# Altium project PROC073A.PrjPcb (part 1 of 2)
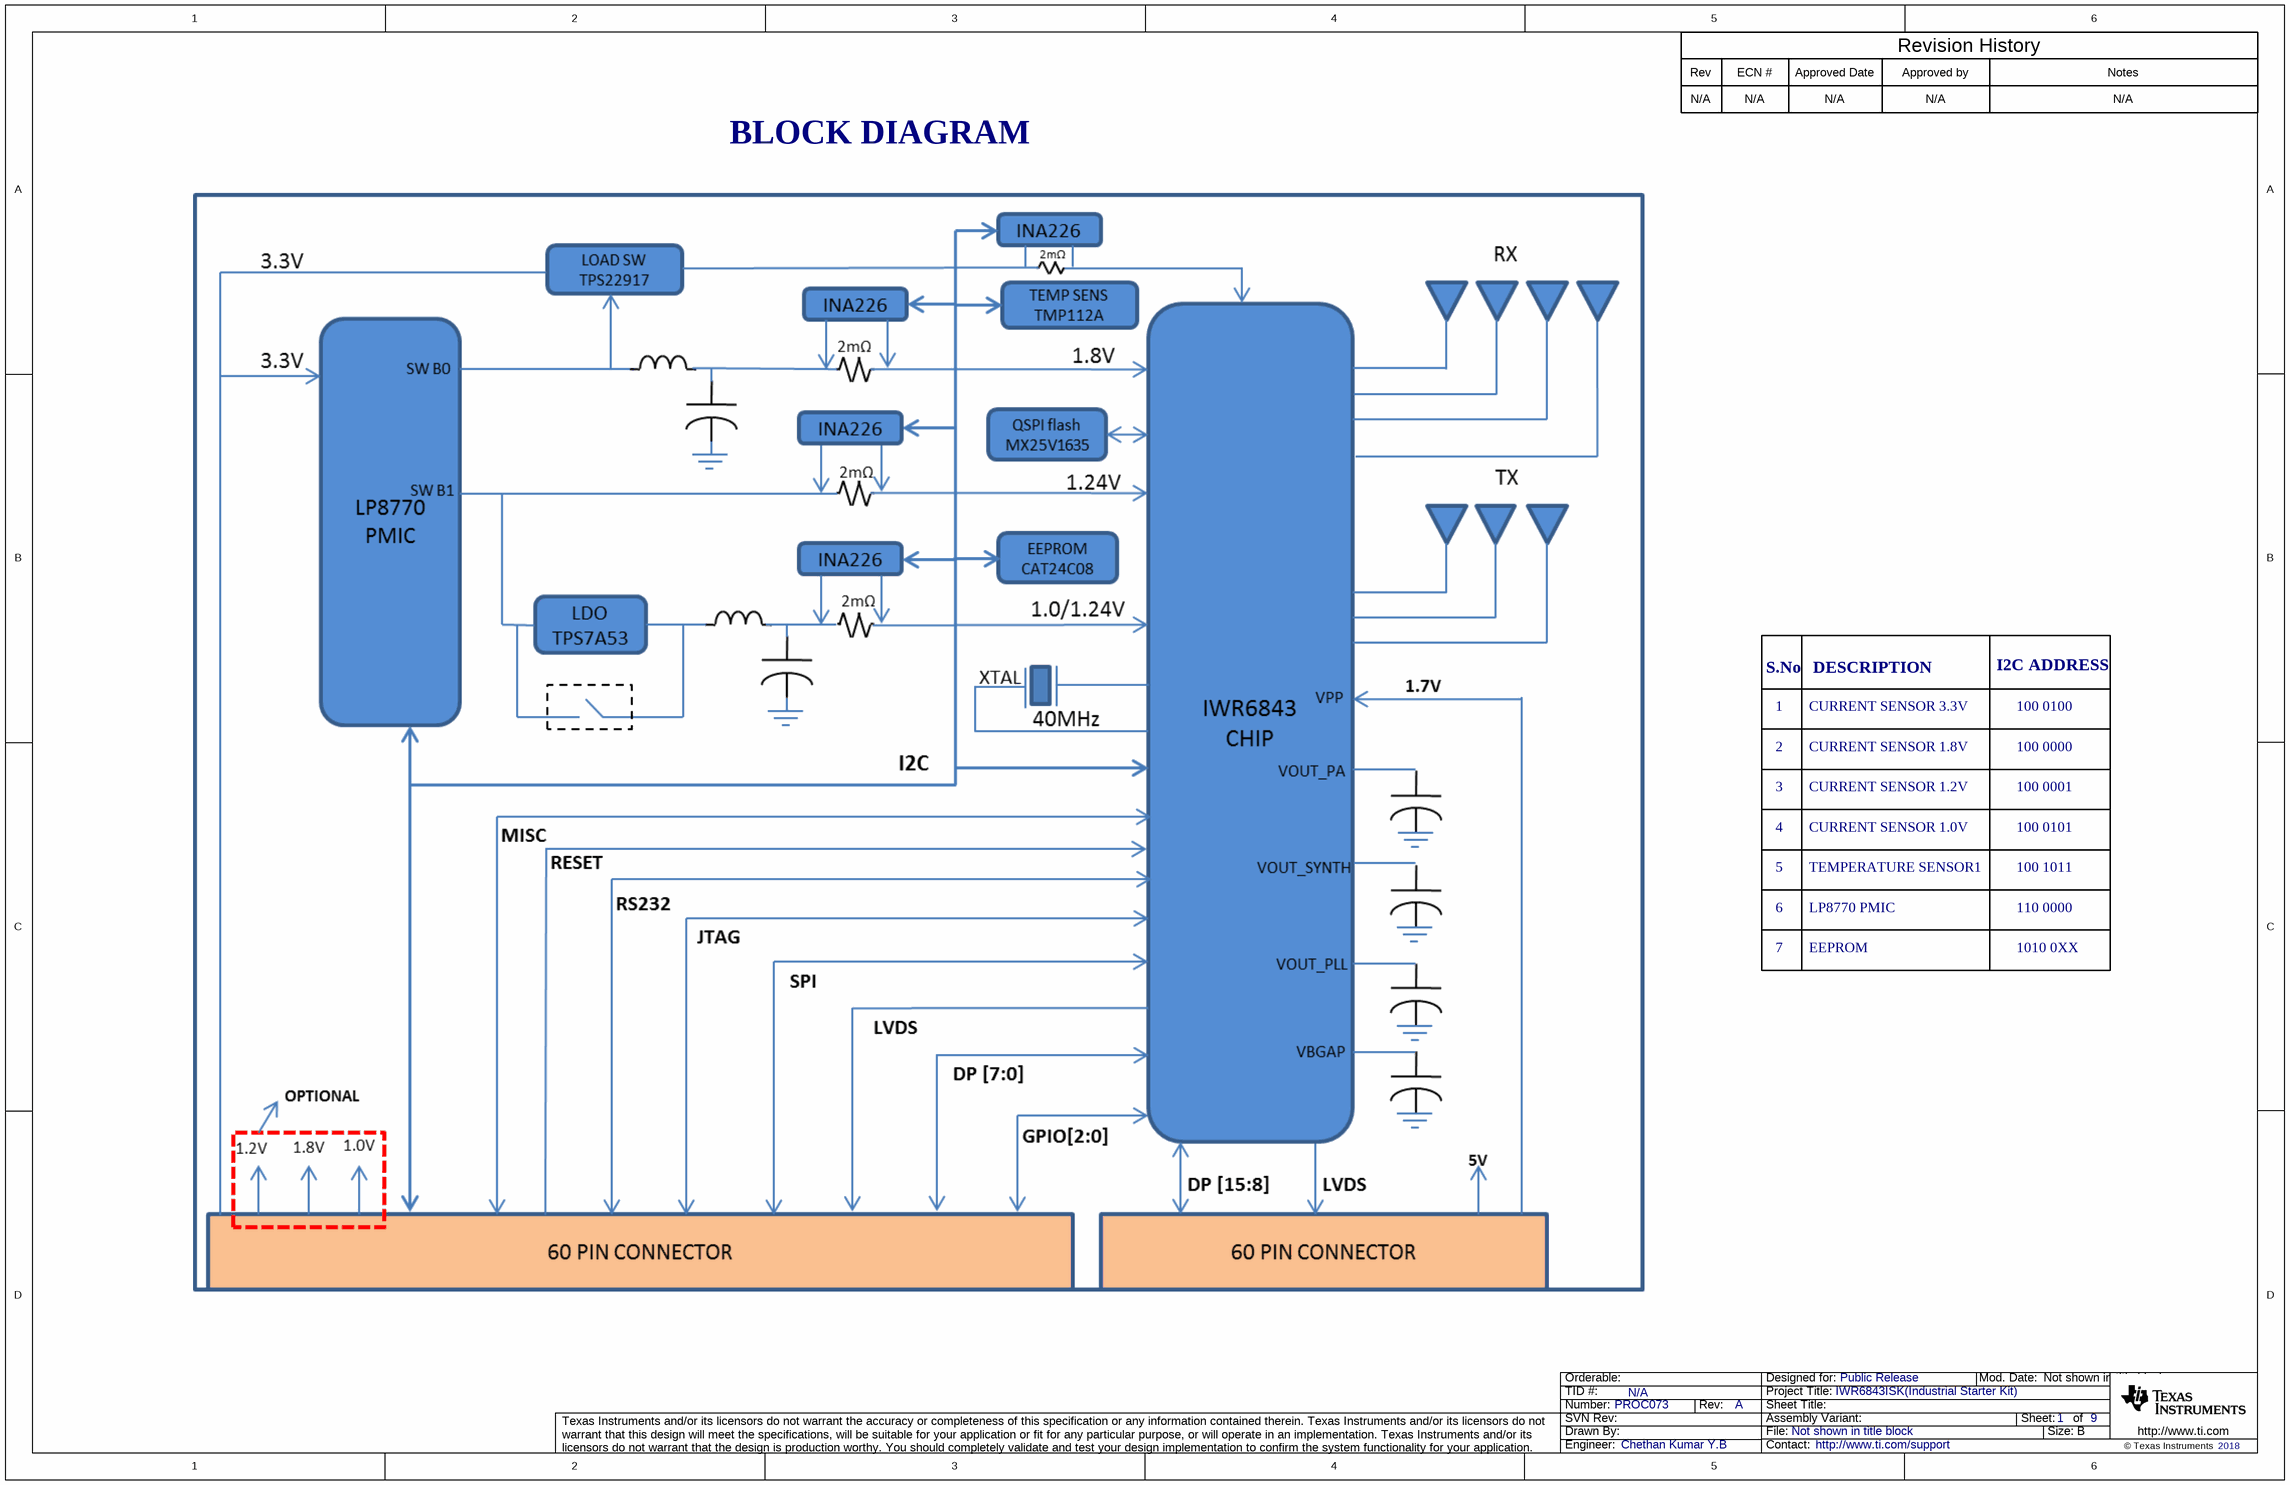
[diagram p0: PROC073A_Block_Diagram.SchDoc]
CopyrightYear: 2018; PCB_Layout: Tessolve; PCB_Rev: A; PRJ_Customer: Public Release; PRJ_Engineer: Chethan Kumar Y.B; PRJ_Number: PROC073; PRJ_Title: IWR6843ISK(Industrial Starter Kit); SCH_Rev: A; TechSupport: http://www.ti.com/support; TID: N/A
9 sheets, 285 parts. Net scope: flat (ports and power ports of the same name join across sheets).
Board file: PROC073A_PCB.PcbDoc
Sheets:
  PROC073A_Block_Diagram.SchDoc
  PROC073A_Table_Of_Contents.SchDoc
  PROC073A_PMIC.SchDoc
  PROC073A_IWR6843_Chip.SchDoc
  PROC073A_Decoupling_caps.SchDoc
  PROC073A_QSPI_Flash_section.SchDoc
  PROC073A_HD_Connector_60Pin.SchDoc
  PROC073A_Temp_Current_sensor.SchDoc
  PROC073A_EVM_Hardware.SchDoc

## Sheet PROC073A_Block_Diagram.SchDoc
size 431 x 279 mm; Date: Not shown in title block; ApprovedBy: Not shown in title block; CheckedBy: Not shown in title block; Author: Not shown in title block; CompanyName: Not shown in title block; Engineer: Not shown in title block; Organization: Not shown in title block; Address1: Not shown in title block; Address2: Not shown in title block; Address3: Not shown in title block; Address4: Not shown in title block; DocumentNumber: 1; Revision: Use project parameter SCH_Rev; SheetNumber: 1; SheetTotal: 9; PageSetup: Record=PageOptions¦CenterHorizontal=True¦CenterVertical=True¦PrintScale=1.00¦XCorrection=1.00¦YCorrection=1.00¦PrintKind=0¦BorderSize=5000000¦LeftOffset=0¦BottomOffset=0¦Orientation=2¦PaperLength=1000¦PaperWidth=1000¦Scale=100¦PaperSource=15¦PrintQuality=600¦MediaType=1¦DitherType=10¦PaperKind=Letter¦PrintScaleMode=1

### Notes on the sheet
- Rev
- N/A
- ECN #
- Approved Date
- Approved by
- Revision History
- Notes
- BLOCK DIAGRAM
- S.No
- DESCRIPTION
- I2C ADDRESS
- 1
- 2
- CURRENT SENSOR 3.3V
- CURRENT SENSOR 1.8V
- 100 0100
- 100 0000
- 3
- 4
- CURRENT SENSOR 1.2V
- CURRENT SENSOR 1.0V
- 100 0001
- 100 0101
- 5
- TEMPERATURE SENSOR1
- 100 1011
- 6
- 7
- LP8770 PMIC
- EEPROM
- 1010 0XX
- 110 0000

## Sheet PROC073A_Table_Of_Contents.SchDoc
size 431 x 279 mm; Date: Not shown in title block; ApprovedBy: Not shown in title block; CheckedBy: Not shown in title block; Author: Not shown in title block; CompanyName: Not shown in title block; Engineer: Not shown in title block; Organization: Not shown in title block; Address1: Not shown in title block; Address2: Not shown in title block; Address3: Not shown in title block; Address4: Not shown in title block; DocumentNumber: 1; Revision: Use project parameter SCH_Rev; SheetNumber: 2; SheetTotal: 9; PageSetup: Record=PageOptions¦CenterHorizontal=True¦CenterVertical=True¦PrintScale=1.00¦XCorrection=1.00¦YCorrection=1.00¦PrintKind=0¦BorderSize=5000000¦LeftOffset=0¦BottomOffset=0¦Orientation=2¦PaperLength=1000¦PaperWidth=1000¦Scale=100¦PaperSource=15¦PrintQuality=600¦MediaType=1¦DitherType=10¦PaperKind=Letter¦PrintScaleMode=1
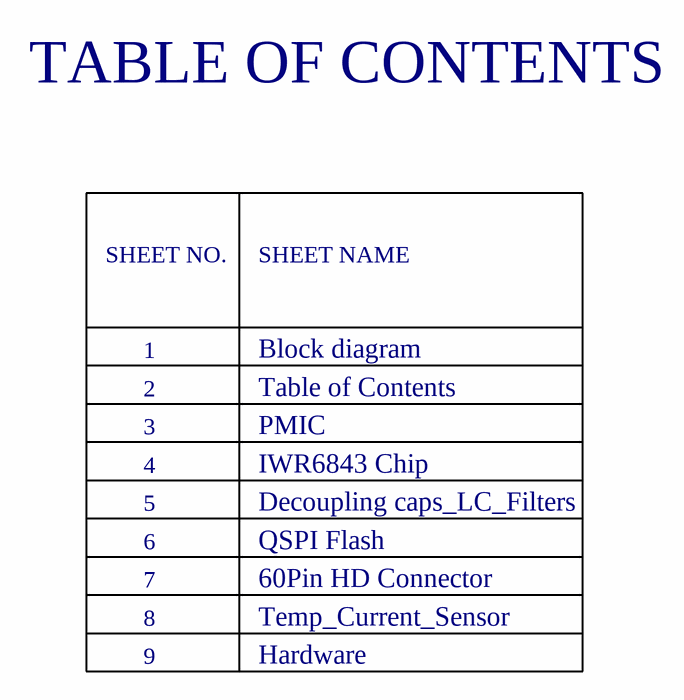
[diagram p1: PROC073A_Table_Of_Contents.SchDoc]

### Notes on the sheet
- TABLE OF CONTENTS
- SHEET NO.
- SHEET NAME
- 1
- 2
- 3
- Table of Contents
- Block diagram
- PMIC
- 4
- 5
- IWR6843 Chip
- Decoupling caps_LC_Filters
- 7
- 8
- 6
- QSPI Flash
- 60Pin HD Connector
- Temp_Current_Sensor
- 9
- Hardware

## Sheet PROC073A_PMIC.SchDoc
size 431 x 279 mm; Date: Not shown in title block; ApprovedBy: Not shown in title block; CheckedBy: Not shown in title block; Author: Not shown in title block; CompanyName: Not shown in title block; Engineer: Not shown in title block; Organization: Not shown in title block; Address1: Not shown in title block; Address2: Not shown in title block; Address3: Not shown in title block; Address4: Not shown in title block; DocumentNumber: 1; Revision: Use project parameter SCH_Rev; SheetNumber: 3; SheetTotal: 9; PageSetup: Record=PageOptions¦CenterHorizontal=True¦CenterVertical=True¦PrintScale=1.00¦XCorrection=1.00¦YCorrection=1.00¦PrintKind=0¦BorderSize=5000000¦LeftOffset=0¦BottomOffset=0¦Orientation=2¦PaperLength=1000¦PaperWidth=1000¦Scale=100¦PaperSource=15¦PrintQuality=600¦MediaType=1¦DitherType=10¦PaperKind=Letter¦PrintScaleMode=1
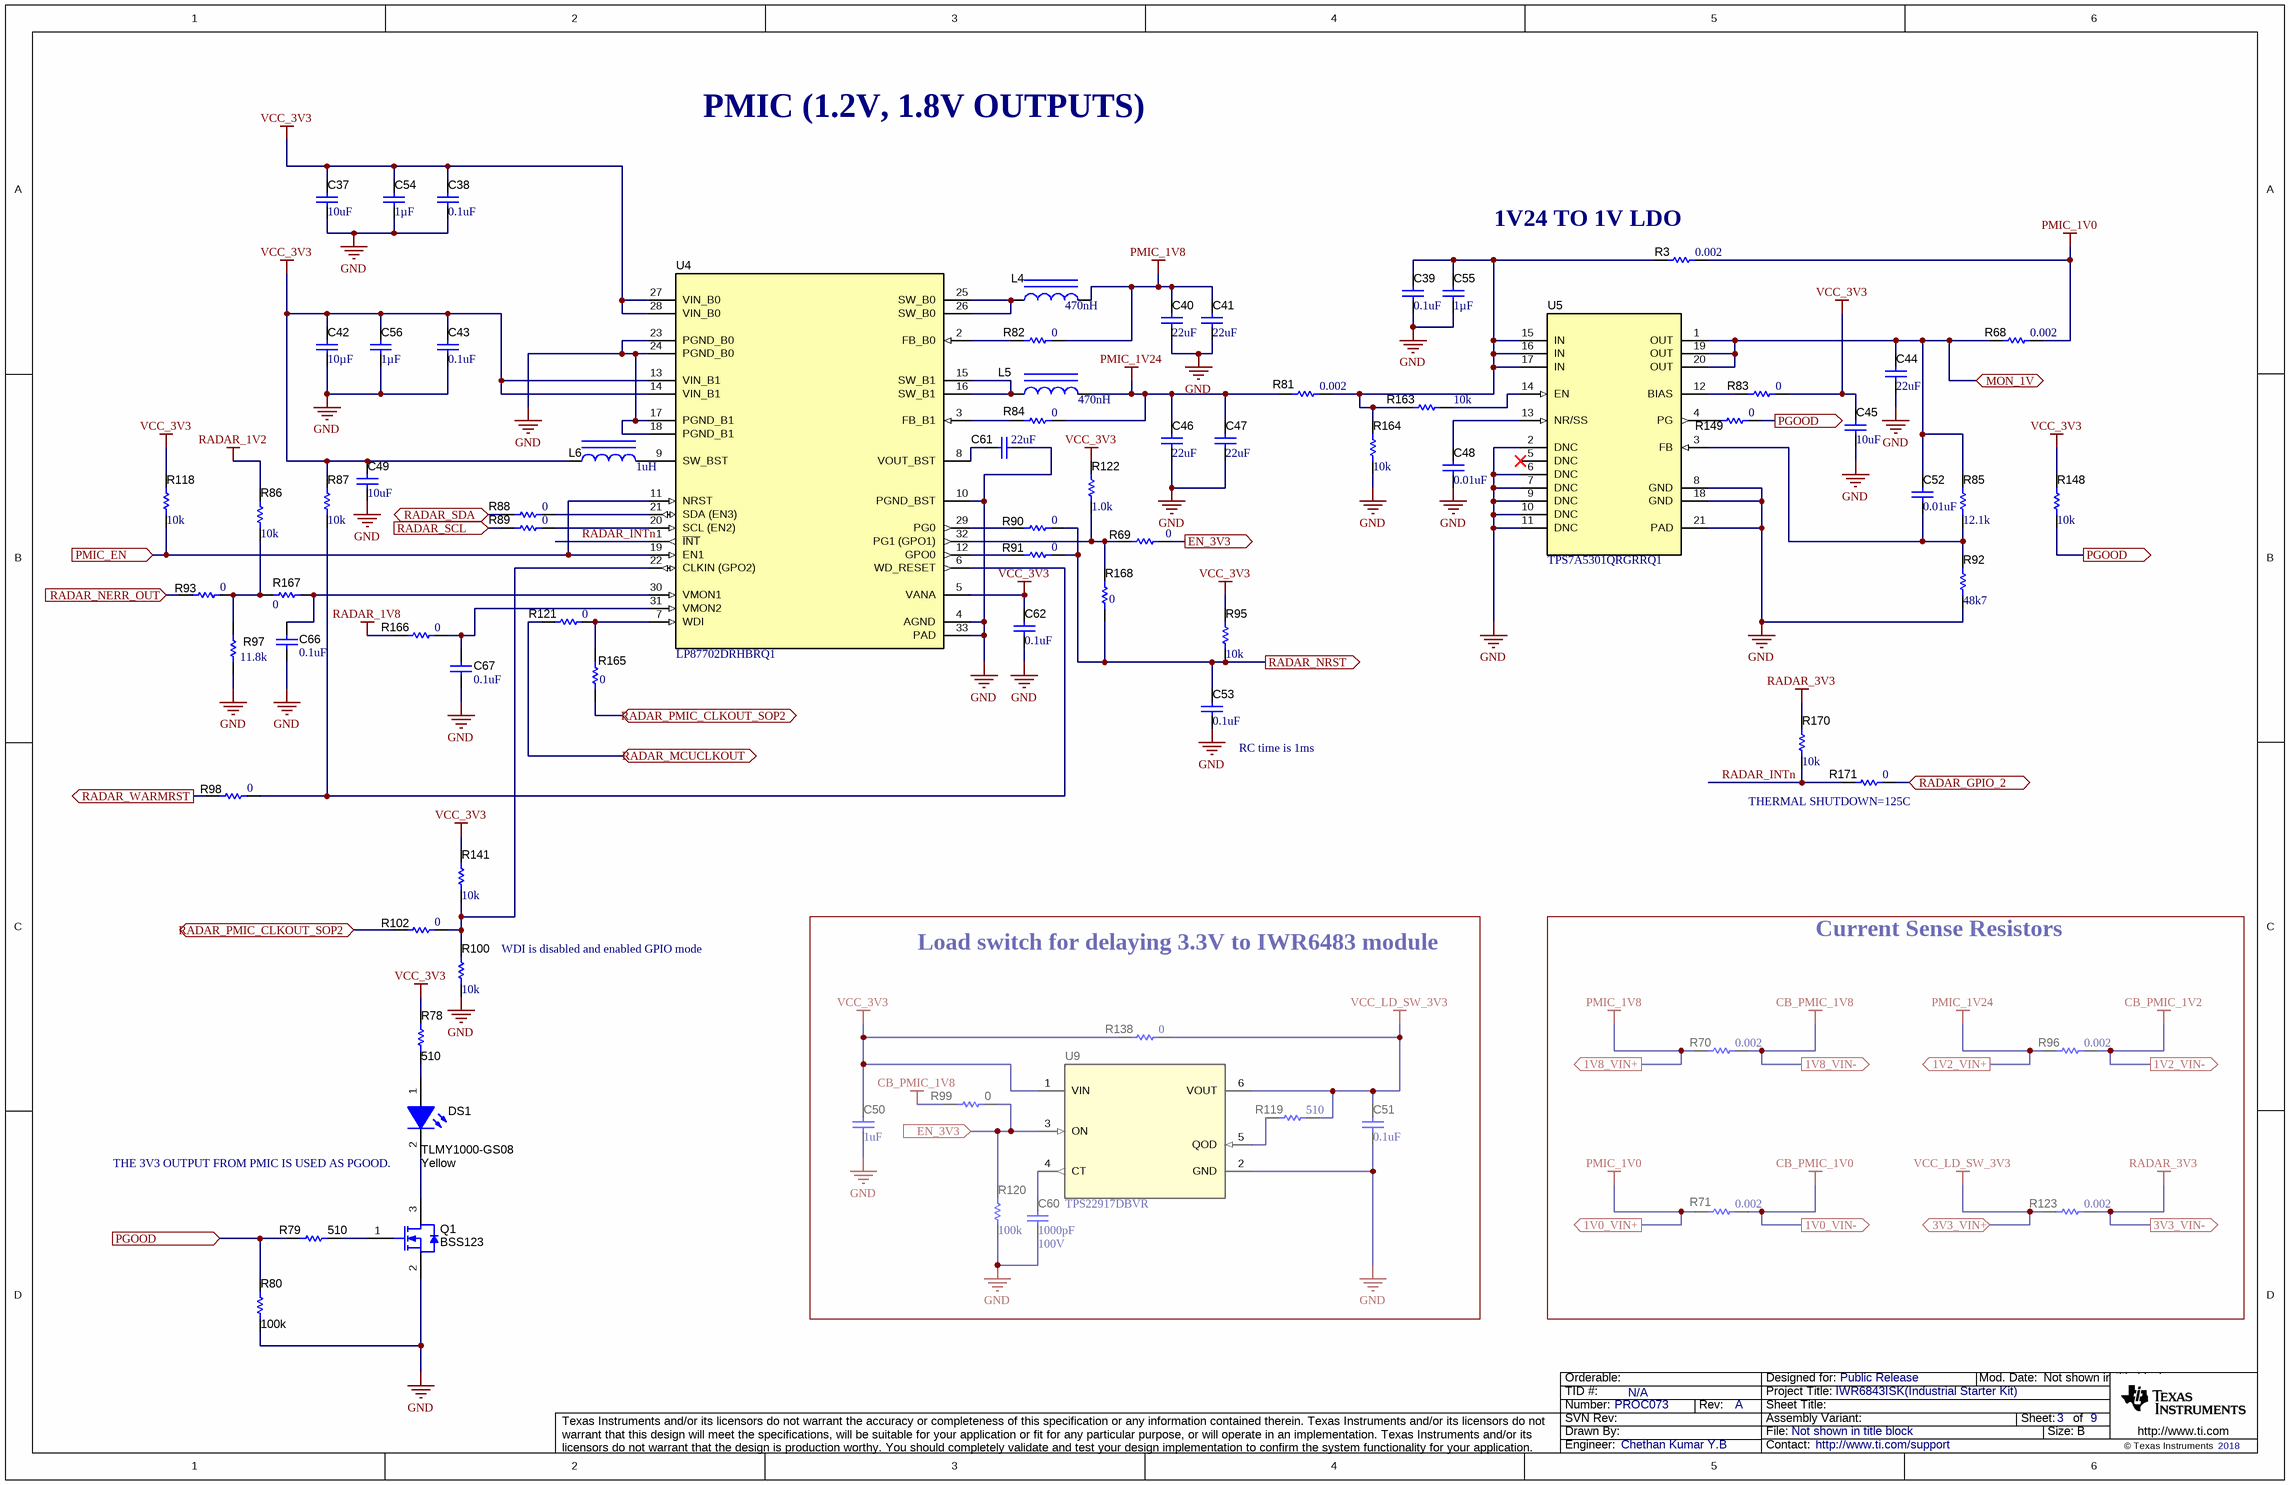
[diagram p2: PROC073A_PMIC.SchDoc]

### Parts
C37  value 10uF  [0805_HV]  (hidden comment: CL21B106KOQNNNE)
C38  value 0.1uF  [0402]  (hidden comment: 0402YC104KAT2A)
C39  ValueDisplayed: 0.1uF  [0402]  (hidden comment: 0402YC104KAT2A)
C40  ValueDisplayed: 22uF  [0805]  (hidden comment: GCM21BD70J226ME36L)
C41  ValueDisplayed: 22uF  [0805]  (hidden comment: GCM21BD70J226ME36L)
C42  Cap_F: 10µF  [0805_HV1]  (hidden comment: CL21B106KOQNNNE)
C43  value 0.1uF  [0402]  (hidden comment: 0402YC104KAT2A)
C44  ValueDisplayed: 22uF  [0805_HV]  (hidden comment: GCM21BD70J226ME36L)
C45  ValueDisplayed: 10uF  [0805_HV]  (hidden comment: GCM21BR71A106KE22L)
C46  ValueDisplayed: 22uF  [0805]  (hidden comment: GCM21BD70J226ME36L)
C47  ValueDisplayed: 22uF  [0805]  (hidden comment: GCM21BD70J226ME36L)
C48  ValueDisplayed: 0.01uF  [0402]  (hidden comment: GRM155R71C103KA01D)
C49  value 10uF  [0805_HV1]  (hidden comment: CL21B106KOQNNNE)
C50  ValueDisplayed: 1uF  [0603]  (hidden comment: CL10B105KQ8NNNC)
C51  ValueDisplayed: 0.1uF  [0603]  (hidden comment: GRM188R70J104KA01D)
C52  ValueDisplayed: 0.01uF  [0402]  (hidden comment: GRM155R71C103KA01D)
C53  ValueDisplayed: 0.1uF  [0402]  (hidden comment: 0402YC104KAT2A)
C54  ValueDisplayed: 1µF  [0402]  (hidden comment: CGB2A1X6S0J105K033BC)
C55  ValueDisplayed: 1µF  [0402]  (hidden comment: CGB2A1X6S0J105K033BC)
C56  ValueDisplayed: 1µF  [0402]  (hidden comment: CGB2A1X6S0J105K033BC)
C60  VDC_V: 100V  ValueDisplayed: 1000pF  [0402]  (hidden comment: CGA2B3X7S2A102K050BB)
C61  ValueDisplayed: 22uF  [0805_HV]  (hidden comment: GRM219R61C226ME15L)
C62  value 0.1uF  [0402]  (hidden comment: 0402YC104KAT2A)
C66  ValueDisplayed: 0.1uF  [0402]  (hidden comment: 0402YC104KAT2A)
C67  ValueDisplayed: 0.1uF  [0402]  (hidden comment: 0402YC104KAT2A)
DS1  TLMY1000-GS08  value Yellow  [TLMx1000_Yellow]
L4  value 470nH  [DFE252012P]  (hidden comment: DFE252012PD-R47M)
L5  value 470nH  [DFE252012P]  (hidden comment: DFE252012PD-R47M)
L6  value 1uH  [DFE252012P]  (hidden comment: DFE252012PD-1R0M)
Q1  BSS123  [SOT-23]
R3  ValueDisplayed: 0.002  [1206]  (hidden comment: PMR18EZPFV2L00)
R68  ValueDisplayed: 0.002  [1206]  (hidden comment: PMR18EZPFV2L00)
R69  value 0  [0402]  (hidden comment: CRCW04020000Z0ED)
R70  ValueDisplayed: 0.002  [1206]  (hidden comment: PMR18EZPFV2L00)
R71  ValueDisplayed: 0.002  [1206]  (hidden comment: PMR18EZPFV2L00)
R78  ValueDisplayed: 510  [0402L]  (hidden comment: ERJ-2GEJ511X)
R79  ValueDisplayed: 510  [0402L]  (hidden comment: ERJ-2GEJ511X)
R80  ValueDisplayed: 100k  [0402L]  (hidden comment: CRCW0402100KFKED)
R81  ValueDisplayed: 0.002  [1206]  (hidden comment: PMR18EZPFV2L00)
R82  value 0  [0402]  (hidden comment: CRCW04020000Z0ED)
R83  ValueDisplayed: 0  [0402]  (hidden comment: CRCW04020000Z0ED)
R84  value 0  [0402]  (hidden comment: CRCW04020000Z0ED)
R85  value 12.1k  [0402]  (hidden comment: CRCW040212K1FKED)
R86  value 10k  [0402]  (hidden comment: CRCW040210K0JNED)
R87  value 10k  [0402]  (hidden comment: CRCW040210K0JNED)
R88  ValueDisplayed: 0  [0201]  (hidden comment: CRCW02010000Z0ED)
R89  ValueDisplayed: 0  [0201]  (hidden comment: CRCW02010000Z0ED)
R90  value 0  [0402]  (hidden comment: CRCW04020000Z0ED)
R91  value 0  [0402]  (hidden comment: CRCW04020000Z0ED)
R92  Value_Code: 48k7  [0402]  (hidden comment: CRCW040248K7FKED)
R93  Res_ohm: 0  [0402]  (hidden comment: CRCW04020000Z0ED)
R95  value 10k  [0402]  (hidden comment: CRCW040210K0JNED)
R96  ValueDisplayed: 0.002  [1206]  (hidden comment: PMR18EZPFV2L00)
R97  ValueDisplayed: 11.8k  [0402]  (hidden comment: CRCW040211K8FKED)
R98  ValueDisplayed: 0  [0402]  (hidden comment: CRCW04020000Z0ED)
R99  ValueDisplayed: 0  [0603]  (hidden comment: MCT06030Z0000ZP500)
R100  value 10k  [0402]  (hidden comment: CRCW040210K0JNED)
R102  value 0  [0402]  (hidden comment: CRCW04020000Z0ED)
R118  value 10k  [0402]  (hidden comment: CRCW040210K0JNED)
R119  ValueDisplayed: 510  [0402]  (hidden comment: CRCW0402510RJNED)
R120  ValueDisplayed: 100k  [0402]  (hidden comment: ERJ-2RKF1003X)
R121  Res_ohm: 0  [0402]  (hidden comment: CRCW04020000Z0ED)
R122  value 1.0k  [0603]  (hidden comment: RC0603JR-071KL)
R123  ValueDisplayed: 0.002  [1206]  (hidden comment: PMR18EZPFV2L00)
R138  ValueDisplayed: 0  [0603]  (hidden comment: RCS06030000Z0EA)
R141  value 10k  [0402]  (hidden comment: CRCW040210K0JNED)
R148  value 10k  [0402]  (hidden comment: CRCW040210K0JNED)
R149  ValueDisplayed: 0  [0201]  (hidden comment: CRCW02010000Z0ED)
R163  value 10k  [0402]  (hidden comment: CRCW040210K0JNED)
R164  value 10k  [0402]  (hidden comment: CRCW040210K0JNED)
R165  Res_ohm: 0  [0402]  (hidden comment: CRCW04020000Z0ED)
R166  Res_ohm: 0  [0402]  (hidden comment: CRCW04020000Z0ED)
R167  Res_ohm: 0  [0402]  (hidden comment: CRCW04020000Z0ED)
R168  value 0  [0402]  (hidden comment: CRCW04020000Z0ED)
R170  value 10k  [0402]  (hidden comment: CRCW040210K0JNED)
R171  Res_ohm: 0  [0402]  (hidden comment: CRCW04020000Z0ED)
U4  LP87702DRHBRQ1  [RHB0032N]
U5  TPS7A5301QRGRRQ1  [RGR0020A]
U9  TPS22917DBVR  [DBV0006A_N]

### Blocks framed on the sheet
Load switch for delaying 3.3V to IWR6483 module: C50 C51 C60 R99 R119 R120 R138 U9
Current Sense Resistors: R70 R71 R96 R123

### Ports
1V0_VIN+ (out), 1V0_VIN- (out), 1V2_VIN+ (out), 1V2_VIN- (out), 1V8_VIN+ (out), 1V8_VIN- (out), 3V3_VIN+, 3V3_VIN- (out), EN_3V3 (in), EN_3V3 (out), MON_1V, PGOOD (in), PGOOD (out), PMIC_EN (in), RADAR_GPIO_2 (bidir), RADAR_MCUCLKOUT, RADAR_NERR_OUT (in), RADAR_NRST (out), RADAR_PMIC_CLKOUT_SOP2, RADAR_SCL (in), RADAR_SDA (bidir), RADAR_WARMRST (out)

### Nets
CB_PMIC_1V0: R71.2 ; port 1V0_VIN-
CB_PMIC_1V2: R96.2 ; port 1V2_VIN-
CB_PMIC_1V8: R70.2 R99.1 ; port 1V8_VIN-
GND: C37.1 C38.1 C39.1 C40.1 C41.2 C42.2 C43.1 C44.2 C45.1 C46.2 C47.2 C48.1 C49.2 C50.2 C51.2 C53.1 C54.2 C55.2 C56.2 C60.2 C61.2 C62.1 C66.1 C67.1 Q1.2(S) R80.1 R92.1 R97.2 R100.1 R120.1 R164.1 U4.4(AGND) U4.10(PGND_BST) U4.17(PGND_B1) U4.18(PGND_B1) U4.23(PGND_B0) U4.24(PGND_B0) U4.33(PAD) U5.2(DNC) U5.6(DNC) U5.7(DNC) U5.8(GND) U5.9(DNC) U5.10(DNC) U5.11(DNC) U5.18(GND) U5.21(PAD) U9.2(GND)
PMIC_1V0: R3.2 R68.2 R71.1 ; port 1V0_VIN+
PMIC_1V8: C40.2 C41.1 L4.2 R70.1 R82.2 ; port 1V8_VIN+
PMIC_1V24: C46.1 C47.1 L5.2 R81.1 R84.2 R96.1 ; port 1V2_VIN+
RADAR_1V2: R86.2
RADAR_1V8: R166.1
RADAR_3V3: R123.2 R170.2 ; port 3V3_VIN-
VCC_3V3: C37.2 C38.2 C42.1 C43.2 C45.2 C49.1 C50.1 C54.1 C56.1 C62.2 L6.1 R78.2 R83.2 R87.2 R95.2 R118.2 R122.1 R138.1 R141.2 R148.2 U4.5(VANA) U4.13(VIN_B1) U4.14(VIN_B1) U4.27(VIN_B0) U4.28(VIN_B0) U9.1(VIN)
VCC_LD_SW_3V3: C51.1 R119.1 R123.1 R138.2 U9.6(VOUT) ; port 3V3_VIN+
EN_3V3: R69.2 R99.2 R120.2 U9.3(ON) ; port EN_3V3
MON_1V: C44.1 C52.1 R68.1 R85.2 U5.1(OUT) U5.19(OUT) U5.20(OUT) ; port MON_1V
PGOOD: R79.1 R80.2 R148.1 R149.2 ; port PGOOD
PMIC_EN: R118.1 U4.11(NRST) U4.19(EN1) ; port PMIC_EN
RADAR_GPIO_2: R171.2 ; port RADAR_GPIO_2
RADAR_INTn: R170.1 R171.1 U4.1(~{INT})
RADAR_MCUCLKOUT: R121.1 ; port RADAR_MCUCLKOUT
RADAR_NERR_OUT: R93.1 ; port RADAR_NERR_OUT
RADAR_NRST: C53.2 R90.2 R91.2 R95.1 R168.1 ; port RADAR_NRST
RADAR_PMIC_CLKOUT_SOP2: R102.1 R165.1 ; port RADAR_PMIC_CLKOUT_SOP2
RADAR_SCL: R89.1 ; port RADAR_SCL
RADAR_SDA: R88.1 ; port RADAR_SDA
RADAR_WARMRST: R98.1 ; port RADAR_WARMRST
NetC39_2: C39.2 C55.1 R3.1 R81.2 R163.2 R164.2 U5.15(IN) U5.16(IN) U5.17(IN)
NetC48_2: C48.2 U5.13(NR/SS)
NetC52_2: C52.2 R85.1 R92.2 U5.3(FB)
NetC60_1: C60.1 U9.4(CT)
NetC61_1: C61.1 U4.8(VOUT_BST)
NetC66_2: C66.2 R167.2 U4.30(VMON1)
NetC67_2: C67.2 R166.2 U4.31(VMON2)
NetDS1_1: DS1.1(A) R78.1
NetDS1_2: DS1.2(K) Q1.3(D)
NetL4_1: L4.1 U4.25(SW_B0) U4.26(SW_B0)
NetL5_1: L5.1 U4.15(SW_B1) U4.16(SW_B1)
NetL6_2: L6.2 U4.9(SW_BST)
NetQ1_1: Q1.1(G) R79.2
NetR69_1: R69.1 R122.2 R168.2 U4.32(PG1_(GPO1))
NetR82_1: R82.1 U4.2(FB_B0)
NetR83_1: R83.1 U5.12(BIAS)
NetR84_1: R84.1 U4.3(FB_B1)
NetR86_1: R86.1 R93.2 R97.1 R167.1
NetR87_1: R87.1 R98.2 U4.6(WD_RESET)
NetR88_2: R88.2 U4.21(SDA_(EN3))
NetR89_2: R89.2 U4.20(SCL_(EN2))
NetR90_1: R90.1 U4.29(PG0)
NetR91_1: R91.1 U4.12(GPO0)
NetR100_2: R100.2 R102.2 R141.1 U4.22(CLKIN_(GPO2))
NetR119_2: R119.2 U9.5(QOD)
NetR121_2: R121.2 R165.2 U4.7(WDI)
NetR149_1: R149.1 U5.4(PG)
NetR163_1: R163.1 U5.14(EN)

Not connected (* = marked no-connect by the designer): U5 5(DNC)*

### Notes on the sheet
- PMIC (1.2V, 1.8V OUTPUTS)
- (near R3) 1V24 TO 1V LDO
- (near C53) RC time is 1ms
- (near R171) THERMAL SHUTDOWN=125C
- (near R100) WDI is disabled and enabled GPIO mode
- THE 3V3 OUTPUT FROM PMIC IS USED AS PGOOD.

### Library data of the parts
C37 C49 = CMP-0007995-2: CAP, CERM, 10 uF, 16 V, +/- 10%, X7R, 0805; Manufacturer: Samsung Electro-Mechanics; TaMin_C: -55°C; Polarized: N; SizeAreaWB_mm2: 6.75; Value1: Unknown; U/M: EA; TaMax_C: 125°C; SizeZ_mm: 1.45; SizeX_mm: 2; SizeY_mm: 1.25; Cap_Case: 0805; Value2: 16V; SizeArea_mm2: 2.5; CompType: Capacitor; Cap_F: 10µF; AEC Category: Q200
C38 C43 C62 = CMP-0006201-2: CAP, CERM, 0.1 uF, 16 V, +/- 10%, X7R, 0402; Manufacturer: AVX; TaMin_C: -55°C; Polarized: N; SizeAreaWB_mm2: 3; Value1: Unknown; U/M: EA; TaMax_C: 125°C; SizeZ_mm: 0.6; SizeX_mm: 1; SizeY_mm: 0.5; Value2: 16V; CompType: Capacitor; Cap_F: 100nF; AEC Category: Q200
C39 C53 C66 C67 = CMP-0006201-2: CAP, CERM, 0.1 uF, 16 V, +/- 10%, X7R, 0402; Manufacturer: AVX; TaMin_C: -55°C; Polarized: N; SizeAreaWB_mm2: 3; Value1: Unknown; U/M: EA; Value: 0.1uF; TaMax_C: 125°C; SizeZ_mm: 0.6; SizeX_mm: 1; SizeY_mm: 0.5; Value2: 16V; CompType: Capacitor; Cap_F: 100nF; AEC Category: Q200
C40 C41 C46 C47 = CMP-0008015-1: CAP, CERM, 22 uF, 6.3 V, +/- 20%, X7T, AEC-Q200 Grade 1, 0805; Manufacturer: MuRata; TaMin_C: -55°C; Polarized: N; SizeAreaWB_mm2: 6.75; Value1: Unknown; U/M: EA; Value: 22uF; TaMax_C: 125°C; SizeZ_mm: 1.45; SizeX_mm: 2; SizeY_mm: 1.25; Value2: 6.3V; SizeArea_mm2: 2.5; CompType: Capacitor; AEC Qualified: Y; Cap_F: 22µF; AEC Grade: 1; AEC Category: Q200
C42 = CMP-0007995-2: CAP, CERM, 10 uF, 16 V, +/- 10%, X7R, 0805; Manufacturer: Samsung Electro-Mechanics; TaMin_C: -55°C; Polarized: N; SizeAreaWB_mm2: 6.75; Value1: Unknown; U/M: EA; Value: 10uF; TaMax_C: 125°C; SizeZ_mm: 1.45; SizeX_mm: 2; SizeY_mm: 1.25; Cap_Case: 0805; Value2: 16V; SizeArea_mm2: 2.5; CompType: Capacitor; AEC Category: Q200
C44 = CMP-0008015-1: CAP, CERM, 22 uF, 6.3 V, +/- 20%, X7T, AEC-Q200 Grade 1, 0805; Manufacturer: MuRata; TaMin_C: -55°C; Polarized: N; SizeAreaWB_mm2: 6.75; Value1: Unknown; U/M: EA; Value: 22uF; TaMax_C: 125°C; SizeZ_mm: 1.45; SizeX_mm: 2; SizeY_mm: 1.25; Cap_Case: 0805; Value2: 6.3V; SizeArea_mm2: 2.5; CompType: Capacitor; AEC Qualified: Y; Cap_F: 22µF; AEC Grade: 1; AEC Category: Q200
C45 = CMP-0008017-2: CAP, CERM, 10 uF, 10 V, +/- 10%, X7R, 0805; Manufacturer: MuRata; TaMin_C: -55°C; Polarized: N; SizeAreaWB_mm2: 6.75; Value1: Unknown; U/M: EA; Value: 10uF; TaMax_C: 125°C; SizeZ_mm: 1.45; SizeX_mm: 2; SizeY_mm: 1.25; Cap_Case: 0805; Value2: 10V; SizeArea_mm2: 2.5; CompType: Capacitor; Cap_F: 10µF; AEC Category: Q200
C48 = CMP-0006639-2: CAP, CERM, 0.01 uF, 16 V, +/- 10%, X7R, 0402; Manufacturer: MuRata; TaMin_C: -55°C; Polarized: N; SizeAreaWB_mm2: 3; Value1: Unknown; U/M: EA; Value: 0.01uF; TaMax_C: 125°C; SizeZ_mm: 0.6; SizeX_mm: 1; SizeY_mm: 0.5; Value2: 16V; CompType: Capacitor; Cap_F: 10nF; AEC Category: Q200
C50 = CMP-0007111-4: CAP, CERM, 1 uF, 6.3 V, +/- 10%, X7R, 0603; Manufacturer: Samsung Electro-Mechanics; TaMin_C: -55°C; Polarized: N; SizeAreaWB_mm2: 4.68; Value1: Unknown; U/M: EA; Value: 1uF; TaMax_C: 125°C; SizeZ_mm: 1; SizeX_mm: 1.6; SizeY_mm: 0.8; Value2: 6.3V; SizeArea_mm2: 1.28; CompType: Capacitor; Cap_F: 1µF; AEC Category: Q200
C51 = CMP-0007359-4: CAP, CERM, 0.1 uF, 6.3 V, +/- 10%, X7R, 0603; Manufacturer: MuRata; TaMin_C: -55°C; Polarized: N; SizeAreaWB_mm2: 4.68; Value1: Unknown; U/M: EA; Value: 0.1uF; TaMax_C: 125°C; SizeZ_mm: 1; SizeX_mm: 1.6; SizeY_mm: 0.8; Value2: 6.3V; SizeArea_mm2: 1.28; CompType: Capacitor; Cap_F: 100nF; AEC Category: Q200
C52 = CMP-0006639-2: CAP, CERM, 0.01 uF, 16 V, +/- 10%, X7R, 0402; Manufacturer: MuRata; TaMin_C: -55°C; Polarized: N; SizeAreaWB_mm2: 3; Value1: Unknown; U/M: EA; Value: 0.01uF; TaMax_C: 125°C; SizeZ_mm: 0.6; SizeX_mm: 1; SizeY_mm: 0.5; Value2: 16V; CompType: Capacitor; Cap_F: 10nF; AEC Category: Q200; INSTALLATION: DNP
C54-C56 = CMP-0081763-1: CAP, CERM, 1 µF, 6.3 V,+/- 10%, X6S, 0402; Manufacturer: TDK; TaMin_C: -55°C; Polarized: N; SizeAreaWB_mm2: 3; U/M: EA; Value: 1uF; TaMax_C: 105°C; SizeZ_mm: 0.6; SizeX_mm: 1; SizeY_mm: 0.5; Value2: 6.3V; CompType: Capacitor; AEC Category: Q200
C60 = CMP-0006332-2: CAP, CERM, 1000 pF, 100 V, +/- 10%, X7S, AEC-Q200 Grade 1, 0402; Manufacturer: TDK; TaMin_C: -55°C; ESR_ohm: 2.71151; Polarized: N; SizeAreaWB_mm2: 3; Value1: 2.71151 ohm; U/M: EA; Value: 1000pF; TaMax_C: 125°C; SizeZ_mm: 0.6; SizeX_mm: 1; SizeY_mm: 0.5; AEC Qualified: Y; Cap_F: 1nF; IRMS_A: 2.64589dA; AEC Category: Q200
C61 = CMP-0008203-2: CAP, CERM, 22 uF, 16 V, +/- 20%, X5R, 0805; Manufacturer: MuRata; TaMin_C: -55°C; Polarized: N; SizeAreaWB_mm2: 6.75; Value1: Unknown; U/M: EA; Value: 22uF; TaMax_C: 85°C; SizeZ_mm: 1.45; SizeX_mm: 2; SizeY_mm: 1.25; Cap_Case: 0805; Value2: 16V; SizeArea_mm2: 2.5; CompType: Capacitor; Cap_F: 22µF; AEC Category: Q200
DS1 = CMP-0078196-1: LED, Yellow, SMD; Manufacturer: Vishay-Semiconductor; Tjmax_C: 120°C; SizeAreaWB_mm2: 4.68; Vr_V: 6V; Power_TotalModule: 40mW; Angle: 160; SizeArea_mm2: 1.28; Ir_A: 10µA; SizeZ_mm: 0.65; Io_A: 2mA; Vf_V: 1.8V; SizeY_mm: 0.8; U/M: EA; Value1: .04W; SizeX_mm: 1.6; Type: AlInGaP
L4 L5 = CMP-0058944-1: Inductor, Shielded, 470 nH, 4.7 A, 0.021 ohm, SMD; Manufacturer: MuRata Toko; Isat: 6.1A @ 30% inductance drop; Irms: 4.7A @ 40C rise; SizeAreaWB_mm2: 10.5; DCR_ohm: 0.021; Imax_A: 4.7A; SizeZ_mm: 1.2; SizeX_mm: 2.5; SizeY_mm: 2; SizeArea_mm2: 5; AEC Category: Q200
L6 = CMP-0058938-1: Inductor, Shielded, 1 uH, 3.8 A, 0.035 ohm, AEC-Q200 Grade 1, SMD; Manufacturer: MuRata Toko; Isat: 4.5A @ 30% inductance drop; Irms: 3.8A @ 40C rise; SizeAreaWB_mm2: 10.5; DCR_ohm: 0.035; Imax_A: 3.8A; SizeZ_mm: 1.2; SizeX_mm: 2.5; SizeY_mm: 2; SizeArea_mm2: 5; Ind_H: 1µH; AEC Qualified: Y; AEC Grade: 1; AEC Category: Q200
Q1 = CMP-0000947-2: MOSFET, N-CH, 100 V, 0.17 A, SOT-23; Alternate Manufacturer: None; Manufacturer: Fairchild Semiconductor; SizeZ_mm: 1.1; ChType: N; Value2: 1.8 nC; Value1: 1; VdsMax_V: 100V; SizeX_mm: 2.5; SizeY_mm: 3; Vgs_V: 20V; Value: 100V; Rdson45_ohm: 10; SizeArea_mm2: 7.5; AEC Category: Q101; IdsMax_A: 1.7dA; SizeAreaWB_mm2: 14; U/M: EA; QgTyp_nC: 1.8
R3 = CMP-0081623-1: RES, 0.002, 1%, 1 W, AEC-Q200 Grade 0, 1206; Manufacturer: Rohm; Value_Code: 2L000; SizeAreaWB_mm2: 10.92; SizeArea_mm2: 5.12; AEC Qualified: Y; AEC Category: Q200; Res_ohm: 2m; Value: 0.002; SizeZ_mm: 1.35; Green_REACh: Incomplete; TempCo: 100 ppm/C; AEC Grade: 0; Power_W: 1W; SizeY_mm: 1.6; Green_Lifecycle: Active; CompType: Resistor; SizeX_mm: 3.2; INSTALLATION: DNP
R68 R70 R71 R81 R96 R123 = CMP-0081623-1: RES, 0.002, 1%, 1 W, AEC-Q200 Grade 0, 1206; Manufacturer: Rohm; Value_Code: 2L000; SizeAreaWB_mm2: 10.92; SizeArea_mm2: 5.12; AEC Qualified: Y; AEC Category: Q200; Res_ohm: 2m; Value: 0.002; SizeZ_mm: 1.35; Green_REACh: Incomplete; TempCo: 100 ppm/C; AEC Grade: 0; Power_W: 1W; SizeY_mm: 1.6; Green_Lifecycle: Active; SizeX_mm: 3.2
R69 R90 R102 = CMP-0026822-3: RES, 0, 5%, 0.063 W, AEC-Q200 Grade 0, 0402; Manufacturer: Vishay-Dale; Power_W: 63mW; TempCo: 200 ppm/C; Value_Code: 0000; EIA_Code: E24; SizeX_mm: 1; SizeY_mm: 0.5; SizeZ_mm: 0.6; Value2: 0.063W; CompType: Resistor; AEC Qualified: Y; VDC_V: 50V; AEC Category: Q200; INSTALLATION: DNP
R78 R79 = CMP-0078212-1: RES, 510, 5%, 0.1 W, AEC-Q200 Grade 0, 0402; Manufacturer: Panasonic; Value_Code: 510R; SizeArea_mm2: 0.5; AEC Qualified: Y; AEC Category: Q200; Value: 510; SizeZ_mm: 0.6; EIA_Code: E24; TempCo: 200 ppm/C; AEC Grade: 0; Power_W: 100mW; VDC_V: 50V; Value2: 0.1W; U/M: EA; SizeX_mm: 1
R80 = CMP-0025950-2: RES, 100 k, 1%, 0.063 W, 0402; Manufacturer: Vishay-Dale; Power_W: 63mW; TempCo: 100 ppm/C; U/M: EA; Value: 100k; EIA_Code: E96; SizeX_mm: 1; SizeY_mm: 0.5; SizeZ_mm: 0.6; Value2: 0.063W; VDC_V: 50V; AEC Category: Q200
R82 R84 R91 R168 = CMP-0026822-3: RES, 0, 5%, 0.063 W, AEC-Q200 Grade 0, 0402; Manufacturer: Vishay-Dale; Power_W: 63mW; TempCo: 200 ppm/C; Value_Code: 0000; EIA_Code: E24; SizeX_mm: 1; SizeY_mm: 0.5; SizeZ_mm: 0.6; Value2: 0.063W; CompType: Resistor; AEC Qualified: Y; VDC_V: 50V; AEC Category: Q200
R83 R121 R166 R171 = CMP-0026822-3: RES, 0, 5%, 0.063 W, AEC-Q200 Grade 0, 0402; Manufacturer: Vishay-Dale; Power_W: 63mW; TempCo: 200 ppm/C; Value_Code: 0000; Value: 0; EIA_Code: E24; SizeX_mm: 1; SizeY_mm: 0.5; SizeZ_mm: 0.6; Value2: 0.063W; CompType: Resistor; AEC Qualified: Y; VDC_V: 50V; AEC Category: Q200
R85 = CMP-0025991-3: RES, 12.1 k, 1%, 0.063 W, AEC-Q200 Grade 0, 0402; Manufacturer: Vishay-Dale; Power_W: 63mW; TempCo: 100 ppm/C; Value_Code: 12k1; EIA_Code: E96; SizeX_mm: 1; SizeY_mm: 0.5; SizeZ_mm: 0.6; Value2: 0.063W; CompType: Resistor; AEC Qualified: Y; VDC_V: 50V; AEC Category: Q200; AEC Grade: 0
R86 R87 R118 R141 R148 R163 R170 = CMP-0026825-5: RES, 10 k, 5%, 0.063 W, AEC-Q200 Grade 0, 0402; Manufacturer: Vishay-Dale; Power_W: 63mW; TempCo: 200 ppm/C; Value_Code: 10k0; EIA_Code: E24; SizeX_mm: 1; SizeY_mm: 0.5; SizeZ_mm: 0.6; Value2: 0.063W; CompType: Resistor; AEC Qualified: Y; VDC_V: 50V; AEC Category: Q200; AEC Grade: 0
R88 R89 R149 = CMP-0027008-4: RES, 0, 5%, 0.05 W, 0201; Manufacturer: Vishay-Dale; Power_W: 50mW; TempCo: ppm/C; Value_Code: 0000; Value: 0; EIA_Code: E24; SizeX_mm: 0.6; SizeY_mm: 0.3; SizeZ_mm: 0.26; Value2: 0.05W; SizeArea_mm2: 0.18; AEC Qualified: N; AEC Category: Q200
R92 = CMP-0026399-2: RES, 48.7 k, 1%, 0.063 W, AEC-Q200 Grade 0, 0402; Manufacturer: Vishay-Dale; Power_W: 63mW; TempCo: 100 ppm/C; Value: 48.7k; EIA_Code: E96; SizeX_mm: 1; SizeY_mm: 0.5; SizeZ_mm: 0.6; Value2: 0.063W; CompType: Resistor; AEC Qualified: Y; VDC_V: 50V; AEC Category: Q200; AEC Grade: 0
R93 R98 R165 R167 = CMP-0026822-3: RES, 0, 5%, 0.063 W, AEC-Q200 Grade 0, 0402; Manufacturer: Vishay-Dale; Power_W: 63mW; TempCo: 200 ppm/C; Value_Code: 0000; Value: 0; EIA_Code: E24; SizeX_mm: 1; SizeY_mm: 0.5; SizeZ_mm: 0.6; Value2: 0.063W; CompType: Resistor; AEC Qualified: Y; VDC_V: 50V; AEC Category: Q200; INSTALLATION: DNP
R95 R100 R164 = CMP-0026825-5: RES, 10 k, 5%, 0.063 W, AEC-Q200 Grade 0, 0402; Manufacturer: Vishay-Dale; Power_W: 63mW; TempCo: 200 ppm/C; Value_Code: 10k0; EIA_Code: E24; SizeX_mm: 1; SizeY_mm: 0.5; SizeZ_mm: 0.6; Value2: 0.063W; CompType: Resistor; AEC Qualified: Y; VDC_V: 50V; AEC Category: Q200; AEC Grade: 0; INSTALLATION: DNP
R97 = CMP-0025978-3: RES, 11.8 k, 1%, 0.063 W, AEC-Q200 Grade 0, 0402; Manufacturer: Vishay-Dale; Power_W: 63mW; TempCo: 100 ppm/C; Value_Code: 11k8; Value: 11.8k; EIA_Code: E96; SizeX_mm: 1; SizeY_mm: 0.5; SizeZ_mm: 0.6; Value2: 0.063W; CompType: Resistor; AEC Qualified: Y; VDC_V: 50V; AEC Category: Q200; AEC Grade: 0
R99 = CMP-0025884-3: RES, 0, 5%, 0.125 W, 0603; Manufacturer: Vishay/Beyschlag; Power_W: 125mW; TempCo: ppm/C; Value_Code: 0000; U/M: EA; Value: 0; EIA_Code: E24; SizeX_mm: 1.6; SizeY_mm: 0.8; SizeZ_mm: 1; Value2: 0.125W; SizeArea_mm2: 1.28; CompType: Resistor; AEC Qualified: N; AEC Category: Q200; INSTALATION: DNP
R119 = CMP-0026944-3: RES, 510, 5%, 0.063 W, AEC-Q200 Grade 0, 0402; Manufacturer: Vishay-Dale; Power_W: 63mW; TempCo: 200 ppm/C; Value_Code: 510R; Value: 510; EIA_Code: E24; SizeX_mm: 1; SizeY_mm: 0.5; SizeZ_mm: 0.6; Value2: 0.063W; AEC Qualified: Y; VDC_V: 50V; AEC Category: Q200; AEC Grade: 0
R120 = CMP-0026659-1: RES, 100 k, 1%, 0.1 W, 0402; Manufacturer: Panasonic; Power_W: 100mW; TempCo: 100 ppm/C; U/M: EA; Value: 100k; EIA_Code: E96; SizeX_mm: 1; SizeY_mm: 0.5; SizeZ_mm: 0.6; Value2: 0.1W; VDC_V: 50V; AEC Category: Q200
R122 = CMP-0025899-5: RES, 1.0 k, 5%, 0.1 W, 0603; Manufacturer: Yageo; Power_W: 100mW; TempCo: 100 ppm/C; Value_Code: 1k00; EIA_Code: E24; Res_ohm: 1k; SizeX_mm: 1.6; SizeY_mm: 0.8; SizeZ_mm: 1; Value2: 0.1W; SizeArea_mm2: 1.28; CompType: Resistor; AEC Qualified: N; VDC_V: 75V; AEC Category: Q200; SizeAreaWB_mm2: 4.68; INSTALLATION: DNP
R138 = CMP-0081973-1: RES, 0, 0%, 0.25 W, AEC-Q200 Grade 0, 0603; Manufacturer: Vishay-Dale; SizeAreaWB_mm2: 4.68; SizeArea_mm2: 1.28; AEC Qualified: Y; AEC Category: Q200; Value: 0; SizeZ_mm: 1; SizeY_mm: 0.8; Power_W: 250mW; Value2: 0.25W; CompType: Resistor; SizeX_mm: 1.6; INSTALLATION: DNP
U4 = CMP-0078631-1: Boost and Dual Buck Regulators With Diagnostic Functions, RHB0032N (VQFN-32); Manufacturer: Texas Instruments; SizeZ_mm: 0.9; SizeX_mm: 5; AEC Category: Q200; AEC Qualified: Y; SizeArea_mm2: 25; CompType: IC; SizeAreaWB_mm2: 49
U5 = CMP-0077268-2: Automotive 3A High-Accuracy Low-Noise Low-Dropout (LDO) Voltage Regulator, RGR0020A (VQFN-20); Manufacturer: Texas Instruments; SizeAreaWB_mm2: 20.25; SizeZ_mm: 1.0; SizeX_mm: 3.5; SizeArea_mm2: 12.25; CompType: IC; AEC Qualified: Y; AEC Category: Q200
U9 = CMP-0077265-1: 5.5-V, 2-A, 80 mohm Low Leakage Load Switch with RCB and Programmable Rise Time, DBV0006A (SOT-23-6); Alternate PartNumber: TPS22917DBVT; Alternate Manufacturer: Texas Instruments; SizeAreaWB_mm2: 14.82; SizeZ_mm: 1.45; SizeX_mm: 2.8; SizeY_mm: 2.9; SizeArea_mm2: 8.12; CompType: IC; AEC Qualified: N; AEC Category: Q200

## Sheet PROC073A_IWR6843_Chip.SchDoc
size 431 x 279 mm; Date: Not shown in title block; ApprovedBy: Not shown in title block; CheckedBy: Not shown in title block; Author: Not shown in title block; CompanyName: Not shown in title block; Engineer: Not shown in title block; Organization: Not shown in title block; Address1: Not shown in title block; Address2: Not shown in title block; Address3: Not shown in title block; Address4: Not shown in title block; DocumentNumber: 1; Revision: Use project parameter SCH_Rev; SheetNumber: 4; SheetTotal: 9; PageSetup: Record=PageOptions¦CenterHorizontal=True¦CenterVertical=True¦PrintScale=1.00¦XCorrection=1.00¦YCorrection=1.00¦PrintKind=0¦BorderSize=5000000¦LeftOffset=0¦BottomOffset=0¦Orientation=2¦PaperLength=1000¦PaperWidth=1000¦Scale=100¦PaperSource=15¦PrintQuality=600¦MediaType=1¦DitherType=10¦PaperKind=Letter¦PrintScaleMode=1
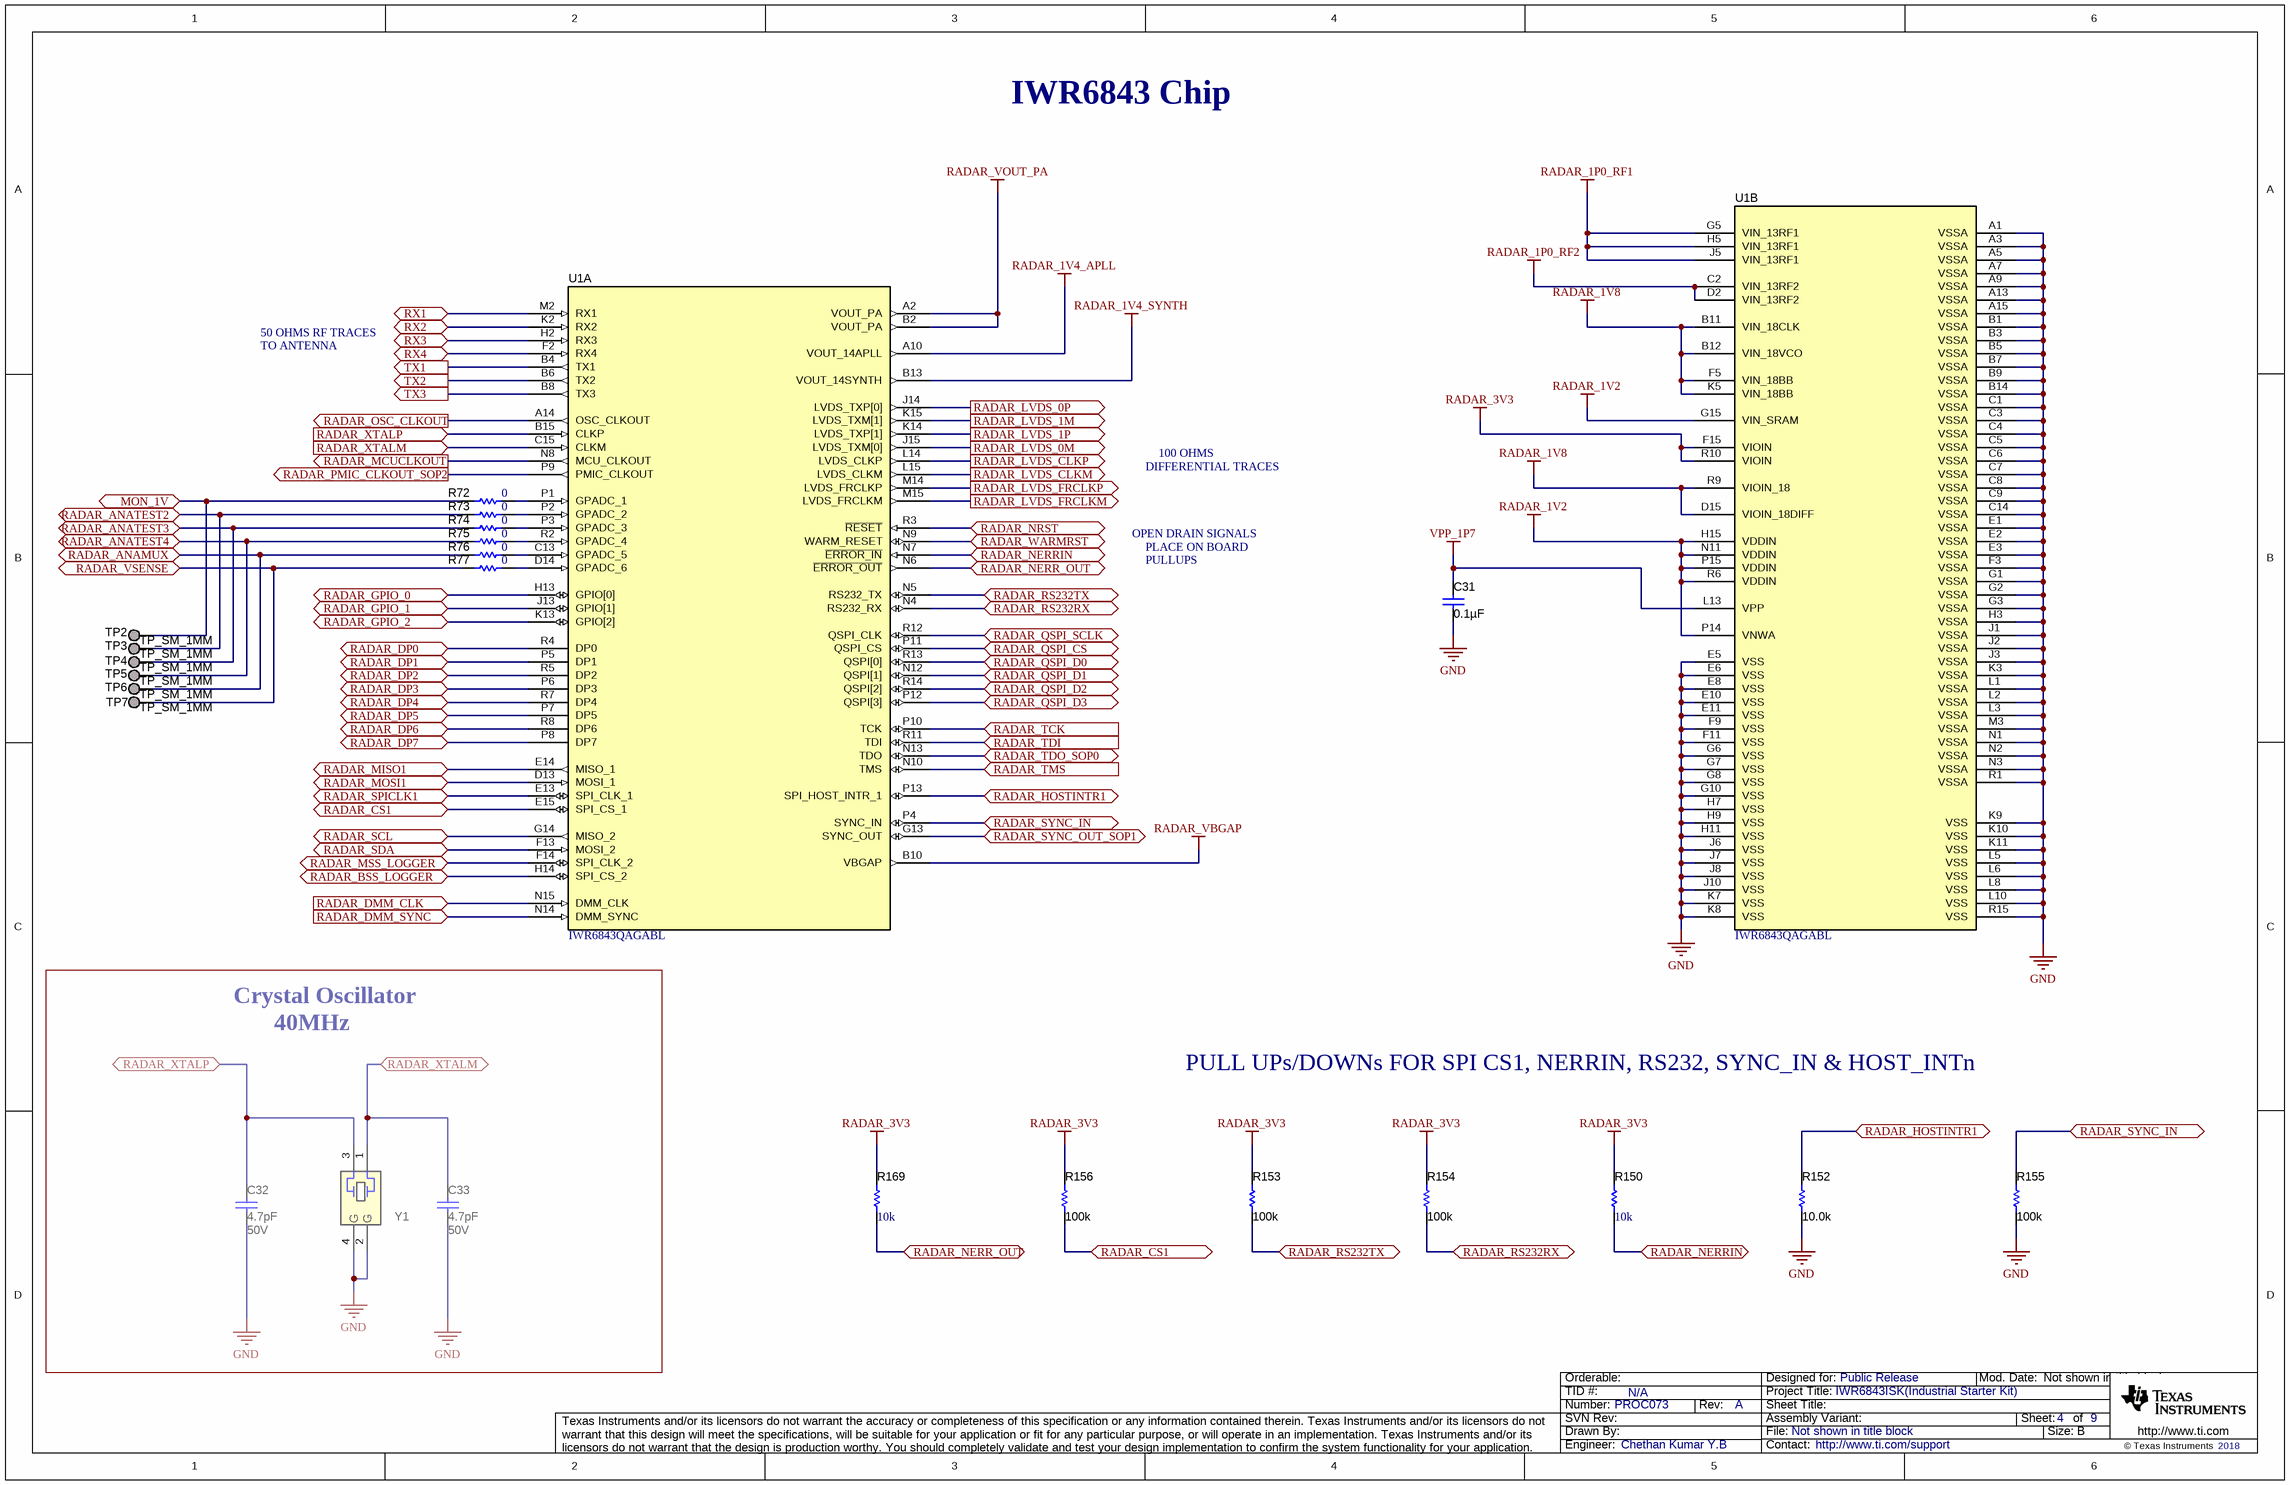
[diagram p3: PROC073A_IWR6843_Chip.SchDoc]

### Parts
C31  ValueDisplayed: 0.1µF  [0201_033]  (hidden comment: C0603X7S1A104K030BC)
C32  VDC_V: 50V  ValueDisplayed: 4.7pF  [0402L]  (hidden comment: GJM1555C1H4R7BB01D)
C33  VDC_V: 50V  ValueDisplayed: 4.7pF  [0402L]  (hidden comment: GJM1555C1H4R7BB01D)
R72  ValueDisplayed: 0  [0402]  (hidden comment: ERJ-2GE0R00X)
R73  ValueDisplayed: 0  [0402]  (hidden comment: ERJ-2GE0R00X)
R74  ValueDisplayed: 0  [0402]  (hidden comment: ERJ-2GE0R00X)
R75  ValueDisplayed: 0  [0402]  (hidden comment: ERJ-2GE0R00X)
R76  ValueDisplayed: 0  [0402]  (hidden comment: ERJ-2GE0R00X)
R77  ValueDisplayed: 0  [0402]  (hidden comment: ERJ-2GE0R00X)
R150  value 10k  [0402]  (hidden comment: CRCW040210K0JNED)
R152  ValueDisplayed: 10.0k  [0402L]  (hidden comment: CRCW040210K0FKED)
R153  ValueDisplayed: 100k  [0402L]  (hidden comment: CRCW0402100KFKED)
R154  ValueDisplayed: 100k  [0402L]  (hidden comment: CRCW0402100KFKED)
R155  ValueDisplayed: 100k  [0402L]  (hidden comment: CRCW0402100KFKED)
R156  ValueDisplayed: 100k  [0402L]  (hidden comment: CRCW0402100KFKED)
R169  value 10k  [0402]  (hidden comment: CRCW040210K0JNED)
TP2  TP_SM_1MM  [TP_SM_1MM]  (no BOM)
TP3  TP_SM_1MM  [TP_SM_1MM]  (no BOM)
TP4  TP_SM_1MM  [TP_SM_1MM]  (no BOM)
TP5  TP_SM_1MM  [TP_SM_1MM]  (no BOM)
TP6  TP_SM_1MM  [TP_SM_1MM]  (no BOM)
TP7  TP_SM_1MM  [TP_SM_1MM]  (no BOM)
U1  IWR6843QAGABL  [ABL0161B]  (parts A,B of 2)
Y1  CX3225SA40000D0PTWCC  [Kyocera_CX3225SA]  (value not drawn)

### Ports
MON_1V, RADAR_ANAMUX, RADAR_ANATEST2, RADAR_ANATEST3, RADAR_ANATEST4, RADAR_BSS_LOGGER, RADAR_CS1, RADAR_CS1 (bidir), RADAR_DMM_CLK (in), RADAR_DMM_SYNC (in), RADAR_DP0 (bidir), RADAR_DP1 (bidir), RADAR_DP2 (bidir), RADAR_DP3 (bidir), RADAR_DP4 (bidir), RADAR_DP5 (bidir), RADAR_DP6 (bidir), RADAR_DP7 (bidir), RADAR_GPIO_0 (bidir), RADAR_GPIO_1 (bidir), RADAR_GPIO_2 (bidir), RADAR_HOSTINTR1, RADAR_LVDS_0M (out), RADAR_LVDS_0P (out), RADAR_LVDS_1M (out), RADAR_LVDS_1P (out), RADAR_LVDS_CLKM (out), RADAR_LVDS_CLKP (out), RADAR_LVDS_FRCLKM (out), RADAR_LVDS_FRCLKP (out), RADAR_MCUCLKOUT (out), RADAR_MISO1, RADAR_MOSI1, RADAR_MSS_LOGGER, RADAR_NERR_OUT, RADAR_NERRIN, RADAR_NRST, RADAR_OSC_CLKOUT (out), RADAR_PMIC_CLKOUT_SOP2 (out), RADAR_QSPI_CS (bidir), RADAR_QSPI_D0 (bidir), RADAR_QSPI_D1 (bidir), RADAR_QSPI_D2 (bidir), RADAR_QSPI_D3 (bidir), RADAR_QSPI_SCLK (bidir), RADAR_RS232RX, RADAR_RS232TX, RADAR_SCL, RADAR_SDA, RADAR_SPICLK1 (bidir), RADAR_SYNC_IN, RADAR_SYNC_OUT_SOP1, RADAR_TCK (in), RADAR_TDI (in), RADAR_TDO_SOP0, RADAR_TMS (in), RADAR_VSENSE, RADAR_WARMRST, RADAR_XTALM, RADAR_XTALM (in), RADAR_XTALP, RADAR_XTALP (in), RX1, RX2, RX3, RX4, TX1 (out), TX2 (out), TX3 (out)

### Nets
GND: C31.1 C32.1 C33.1 R152.1 R155.1 U1.A1(VSSA) U1.A3(VSSA) U1.A5(VSSA) U1.A7(VSSA) U1.A9(VSSA) U1.A13(VSSA) U1.A15(VSSA) U1.B1(VSSA) U1.B3(VSSA) U1.B5(VSSA) U1.B7(VSSA) U1.B9(VSSA) U1.B14(VSSA) U1.C1(VSSA) U1.C3(VSSA) U1.C4(VSSA) U1.C5(VSSA) U1.C6(VSSA) U1.C7(VSSA) U1.C8(VSSA) U1.C9(VSSA) U1.C14(VSSA) U1.E1(VSSA) U1.E2(VSSA) U1.E3(VSSA) U1.E5(VSS) U1.E6(VSS) U1.E8(VSS) U1.E10(VSS) U1.E11(VSS) U1.F3(VSSA) U1.F9(VSS) U1.F11(VSS) U1.G1(VSSA) U1.G2(VSSA) U1.G3(VSSA) U1.G6(VSS) U1.G7(VSS) U1.G8(VSS) U1.G10(VSS) U1.H3(VSSA) U1.H7(VSS) U1.H9(VSS) U1.H11(VSS) U1.J1(VSSA) U1.J2(VSSA) U1.J3(VSSA) U1.J6(VSS) U1.J7(VSS) U1.J8(VSS) U1.J10(VSS) U1.K3(VSSA) U1.K7(VSS) U1.K8(VSS) U1.K9(VSS) U1.K10(VSS) U1.K11(VSS) U1.L1(VSSA) U1.L2(VSSA) U1.L3(VSSA) U1.L5(VSS) U1.L6(VSS) U1.L8(VSS) U1.L10(VSS) U1.M3(VSSA) U1.N1(VSSA) U1.N2(VSSA) U1.N3(VSSA) U1.R1(VSSA) U1.R15(VSS) Y1.2(GND) Y1.4(GND)
RADAR_1P0_RF1: U1.G5(VIN_13RF1) U1.H5(VIN_13RF1) U1.J5(VIN_13RF1)
RADAR_1P0_RF2: U1.C2(VIN_13RF2) U1.D2(VIN_13RF2)
RADAR_1V2: U1.G15(VIN_SRAM) U1.H15(VDDIN) U1.N11(VDDIN) U1.P14(VNWA) U1.P15(VDDIN) U1.R6(VDDIN)
RADAR_1V4_APLL: U1.A10(VOUT_14APLL)
RADAR_1V4_SYNTH: U1.B13(VOUT_14SYNTH)
RADAR_1V8: U1.B11(VIN_18CLK) U1.B12(VIN_18VCO) U1.D15(VIOIN_18DIFF) U1.F5(VIN_18BB) U1.K5(VIN_18BB) U1.R9(VIOIN_18)
RADAR_3V3: R150.2 R153.2 R154.2 R156.2 R169.2 U1.F15(VIOIN) U1.R10(VIOIN)
RADAR_VBGAP: U1.B10(VBGAP)
RADAR_VOUT_PA: U1.A2(VOUT_PA) U1.B2(VOUT_PA)
VPP_1P7: C31.2 U1.L13(VPP)
MON_1V: R72.1 TP2.1 ; port MON_1V
RADAR_ANAMUX: R76.1 TP6.1 ; port RADAR_ANAMUX
RADAR_ANATEST2: R73.1 TP3.1 ; port RADAR_ANATEST2
RADAR_ANATEST3: R74.1 TP4.1 ; port RADAR_ANATEST3
RADAR_ANATEST4: R75.1 TP5.1 ; port RADAR_ANATEST4
RADAR_BSS_LOGGER: U1.H14(SPI_CS_2) ; port RADAR_BSS_LOGGER
RADAR_CS1: R156.1 U1.E15(SPI_CS_1) ; port RADAR_CS1
RADAR_DMM_CLK: U1.N15(DMM_CLK) ; port RADAR_DMM_CLK
RADAR_DMM_SYNC: U1.N14(DMM_SYNC) ; port RADAR_DMM_SYNC
RADAR_DP0: U1.R4(DP0) ; port RADAR_DP0
RADAR_DP1: U1.P5(DP1) ; port RADAR_DP1
RADAR_DP2: U1.R5(DP2) ; port RADAR_DP2
RADAR_DP3: U1.P6(DP3) ; port RADAR_DP3
RADAR_DP4: U1.R7(DP4) ; port RADAR_DP4
RADAR_DP5: U1.P7(DP5) ; port RADAR_DP5
RADAR_DP6: U1.R8(DP6) ; port RADAR_DP6
RADAR_DP7: U1.P8(DP7) ; port RADAR_DP7
RADAR_GPIO_0: U1.H13(GPIO[0]) ; port RADAR_GPIO_0
RADAR_GPIO_1: U1.J13(GPIO[1]) ; port RADAR_GPIO_1
RADAR_GPIO_2: U1.K13(GPIO[2]) ; port RADAR_GPIO_2
RADAR_HOSTINTR1: R152.2 U1.P13(SPI_HOST_INTR_1) ; port RADAR_HOSTINTR1
RADAR_LVDS_0M: U1.J15(LVDS_TXM[0]) ; port RADAR_LVDS_0M
RADAR_LVDS_0P: U1.J14(LVDS_TXP[0]) ; port RADAR_LVDS_0P
RADAR_LVDS_1M: U1.K15(LVDS_TXM[1]) ; port RADAR_LVDS_1M
RADAR_LVDS_1P: U1.K14(LVDS_TXP[1]) ; port RADAR_LVDS_1P
RADAR_LVDS_CLKM: U1.L15(LVDS_CLKM) ; port RADAR_LVDS_CLKM
RADAR_LVDS_CLKP: U1.L14(LVDS_CLKP) ; port RADAR_LVDS_CLKP
RADAR_LVDS_FRCLKM: U1.M15(LVDS_FRCLKM) ; port RADAR_LVDS_FRCLKM
RADAR_LVDS_FRCLKP: U1.M14(LVDS_FRCLKP) ; port RADAR_LVDS_FRCLKP
RADAR_MCUCLKOUT: U1.N8(MCU_CLKOUT) ; port RADAR_MCUCLKOUT
RADAR_MISO1: U1.E14(MISO_1) ; port RADAR_MISO1
RADAR_MOSI1: U1.D13(MOSI_1) ; port RADAR_MOSI1
RADAR_MSS_LOGGER: U1.F14(SPI_CLK_2) ; port RADAR_MSS_LOGGER
RADAR_NERR_OUT: R169.1 U1.N6(~{ERROR_OUT}) ; port RADAR_NERR_OUT
RADAR_NERRIN: R150.1 U1.N7(~{ERROR_IN}) ; port RADAR_NERRIN
RADAR_NRST: U1.R3(~{RESET}) ; port RADAR_NRST
RADAR_OSC_CLKOUT: U1.A14(OSC_CLKOUT) ; port RADAR_OSC_CLKOUT
RADAR_PMIC_CLKOUT_SOP2: U1.P9(PMIC_CLKOUT) ; port RADAR_PMIC_CLKOUT_SOP2
RADAR_QSPI_CS: U1.P11(QSPI_CS) ; port RADAR_QSPI_CS
RADAR_QSPI_D0: U1.R13(QSPI[0]) ; port RADAR_QSPI_D0
RADAR_QSPI_D1: U1.N12(QSPI[1]) ; port RADAR_QSPI_D1
RADAR_QSPI_D2: U1.R14(QSPI[2]) ; port RADAR_QSPI_D2
RADAR_QSPI_D3: U1.P12(QSPI[3]) ; port RADAR_QSPI_D3
RADAR_QSPI_SCLK: U1.R12(QSPI_CLK) ; port RADAR_QSPI_SCLK
RADAR_RS232RX: R154.1 U1.N4(RS232_RX) ; port RADAR_RS232RX
RADAR_RS232TX: R153.1 U1.N5(RS232_TX) ; port RADAR_RS232TX
RADAR_SCL: U1.G14(MISO_2) ; port RADAR_SCL
RADAR_SDA: U1.F13(MOSI_2) ; port RADAR_SDA
RADAR_SPICLK1: U1.E13(SPI_CLK_1) ; port RADAR_SPICLK1
RADAR_SYNC_IN: R155.2 U1.P4(SYNC_IN) ; port RADAR_SYNC_IN
RADAR_SYNC_OUT_SOP1: U1.G13(SYNC_OUT) ; port RADAR_SYNC_OUT_SOP1
RADAR_TCK: U1.P10(TCK) ; port RADAR_TCK
RADAR_TDI: U1.R11(TDI) ; port RADAR_TDI
RADAR_TDO_SOP0: U1.N13(TDO) ; port RADAR_TDO_SOP0
RADAR_TMS: U1.N10(TMS) ; port RADAR_TMS
RADAR_VSENSE: R77.1 TP7.1 ; port RADAR_VSENSE
RADAR_WARMRST: U1.N9(WARM_RESET) ; port RADAR_WARMRST
RADAR_XTALM: C33.2 U1.C15(CLKM) Y1.1 ; port RADAR_XTALM
RADAR_XTALP: C32.2 U1.B15(CLKP) Y1.3 ; port RADAR_XTALP
RX1: U1.M2(RX1) ; port RX1
RX2: U1.K2(RX2) ; port RX2
RX3: U1.H2(RX3) ; port RX3
RX4: U1.F2(RX4) ; port RX4
TX1: U1.B4(TX1) ; port TX1
TX2: U1.B6(TX2) ; port TX2
TX3: U1.B8(TX3) ; port TX3
NetR72_2: R72.2 U1.P1(GPADC_1)
NetR73_2: R73.2 U1.P2(GPADC_2)
NetR74_2: R74.2 U1.P3(GPADC_3)
NetR75_2: R75.2 U1.R2(GPADC_4)
NetR76_2: R76.2 U1.C13(GPADC_5)
NetR77_2: R77.2 U1.D14(GPADC_6)

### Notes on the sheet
- IWR6843 Chip
- 50 OHMS RF TRACES
- TO ANTENNA
- DIFFERENTIAL TRACES
- 100 OHMS
- OPEN DRAIN SIGNALS
- PLACE ON BOARD
- PULLUPS
- Crystal Oscillator
- 40MHz
- PULL UPs/DOWNs FOR SPI CS1, NERRIN, RS232, SYNC_IN & HOST_INTn

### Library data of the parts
C31 = CMP-0078219-1: CAP, CERM, 0.1 µF, 10 V,+/- 10%, X7S, 0201; Manufacturer: TDK; TaMin_C: -55°C; Polarized: N; Green_Lifecycle: NRND; SizeAreaWB_mm2: 2.08; Green_REACh: Passed; U/M: EA; Value: 0.1uF; TaMax_C: 125°C; SizeZ_mm: 0.33; SizeX_mm: 0.6; SizeY_mm: 0.3; Cap_Case: 0201; Value2: 10V; SizeArea_mm2: 0.18; CompType: Capacitor; Cap_F: 100nF; AEC Category: Q200
C32 C33 = CMP-0006367-2: CAP, CERM, 4.7 pF, 50 V, +/- 2%, C0G/NP0, 0402; Manufacturer: MuRata; TaMin_C: -55°C; Polarized: N; SizeAreaWB_mm2: 3; Value1: Unknown; U/M: EA; Value: 4.7pF; TaMax_C: 125°C; SizeZ_mm: 0.6; SizeX_mm: 1; SizeY_mm: 0.5; Cap_Case: 0402; CompType: Capacitor; AEC Category: Q200
R72-R77 = CMP-0026992-3: RES, 0, 5%, 0.1 W, AEC-Q200 Grade 0, 0402; Manufacturer: Panasonic; Power_W: 100mW; TempCo: 600 ppm/C; Value_Code: 0000; Value: 0; EIA_Code: E24; SizeX_mm: 1; SizeY_mm: 0.5; SizeZ_mm: 0.6; Value2: 0.1W; AEC Qualified: Y; VDC_V: 50V; AEC Category: Q200; SizeAreaWB_mm2: 3
R150 R169 = CMP-0026825-5: as R95 on sheet PROC073A_PMIC
R152 = CMP-0025958-2: RES, 10.0 k, 1%, 0.063 W, 0402; Manufacturer: Vishay-Dale; Power_W: 63mW; TempCo: 100 ppm/C; Value_Code: 10k0; U/M: EA; Value: 10.0k; EIA_Code: E96; Res_ohm: 10k; SizeX_mm: 1; SizeY_mm: 0.5; SizeZ_mm: 0.6; Value2: 0.063W; VDC_V: 50V; AEC Category: Q200
R153-R156 = CMP-0025950-2: as R80 on sheet PROC073A_PMIC
TP2-TP7 = CMP-0003825-1: 1mm Test Point, SMT; Manufacturer: Any
U1 = CMP-0081105-1: IWR1843QAGABL, ABL0161B (FCBGA-161); Alternate Manufacturer: Texas Instruments; SizeAreaWB_mm2: 153.76; SizeZ_mm: 1.17; SizeX_mm: 10.4; SizeArea_mm2: 108.16; CompType: IC; AEC Qualified: N; AEC Category: Q200
Y1 = CMP-0004694-3: Crystal, 40 MHz, 8pF, SMD; Manufacturer: Kyocera; TaMin_C: -40°C; Frequency Stability: +/-200ppm; SizeAreaWB_mm2: 14.7; Frequency_Fixed: 40MHz; TaMax_C: 125°C; SizeZ_mm: 0.8; SizeX_mm: 2.5; SizeY_mm: 3.2; SizeArea_mm2: 8

## Sheet PROC073A_Decoupling_caps.SchDoc
size 431 x 279 mm; Date: Not shown in title block; ApprovedBy: Not shown in title block; CheckedBy: Not shown in title block; Author: Not shown in title block; CompanyName: Not shown in title block; Engineer: Not shown in title block; Organization: Not shown in title block; Address1: Not shown in title block; Address2: Not shown in title block; Address3: Not shown in title block; Address4: Not shown in title block; DocumentNumber: 1; Revision: Use project parameter SCH_Rev; SheetNumber: 5; SheetTotal: 9; PageSetup: Record=PageOptions¦CenterHorizontal=True¦CenterVertical=True¦PrintScale=1.00¦XCorrection=1.00¦YCorrection=1.00¦PrintKind=0¦BorderSize=5000000¦LeftOffset=0¦BottomOffset=0¦Orientation=2¦PaperLength=1000¦PaperWidth=1000¦Scale=100¦PaperSource=15¦PrintQuality=600¦MediaType=1¦DitherType=10¦PaperKind=Letter¦PrintScaleMode=1
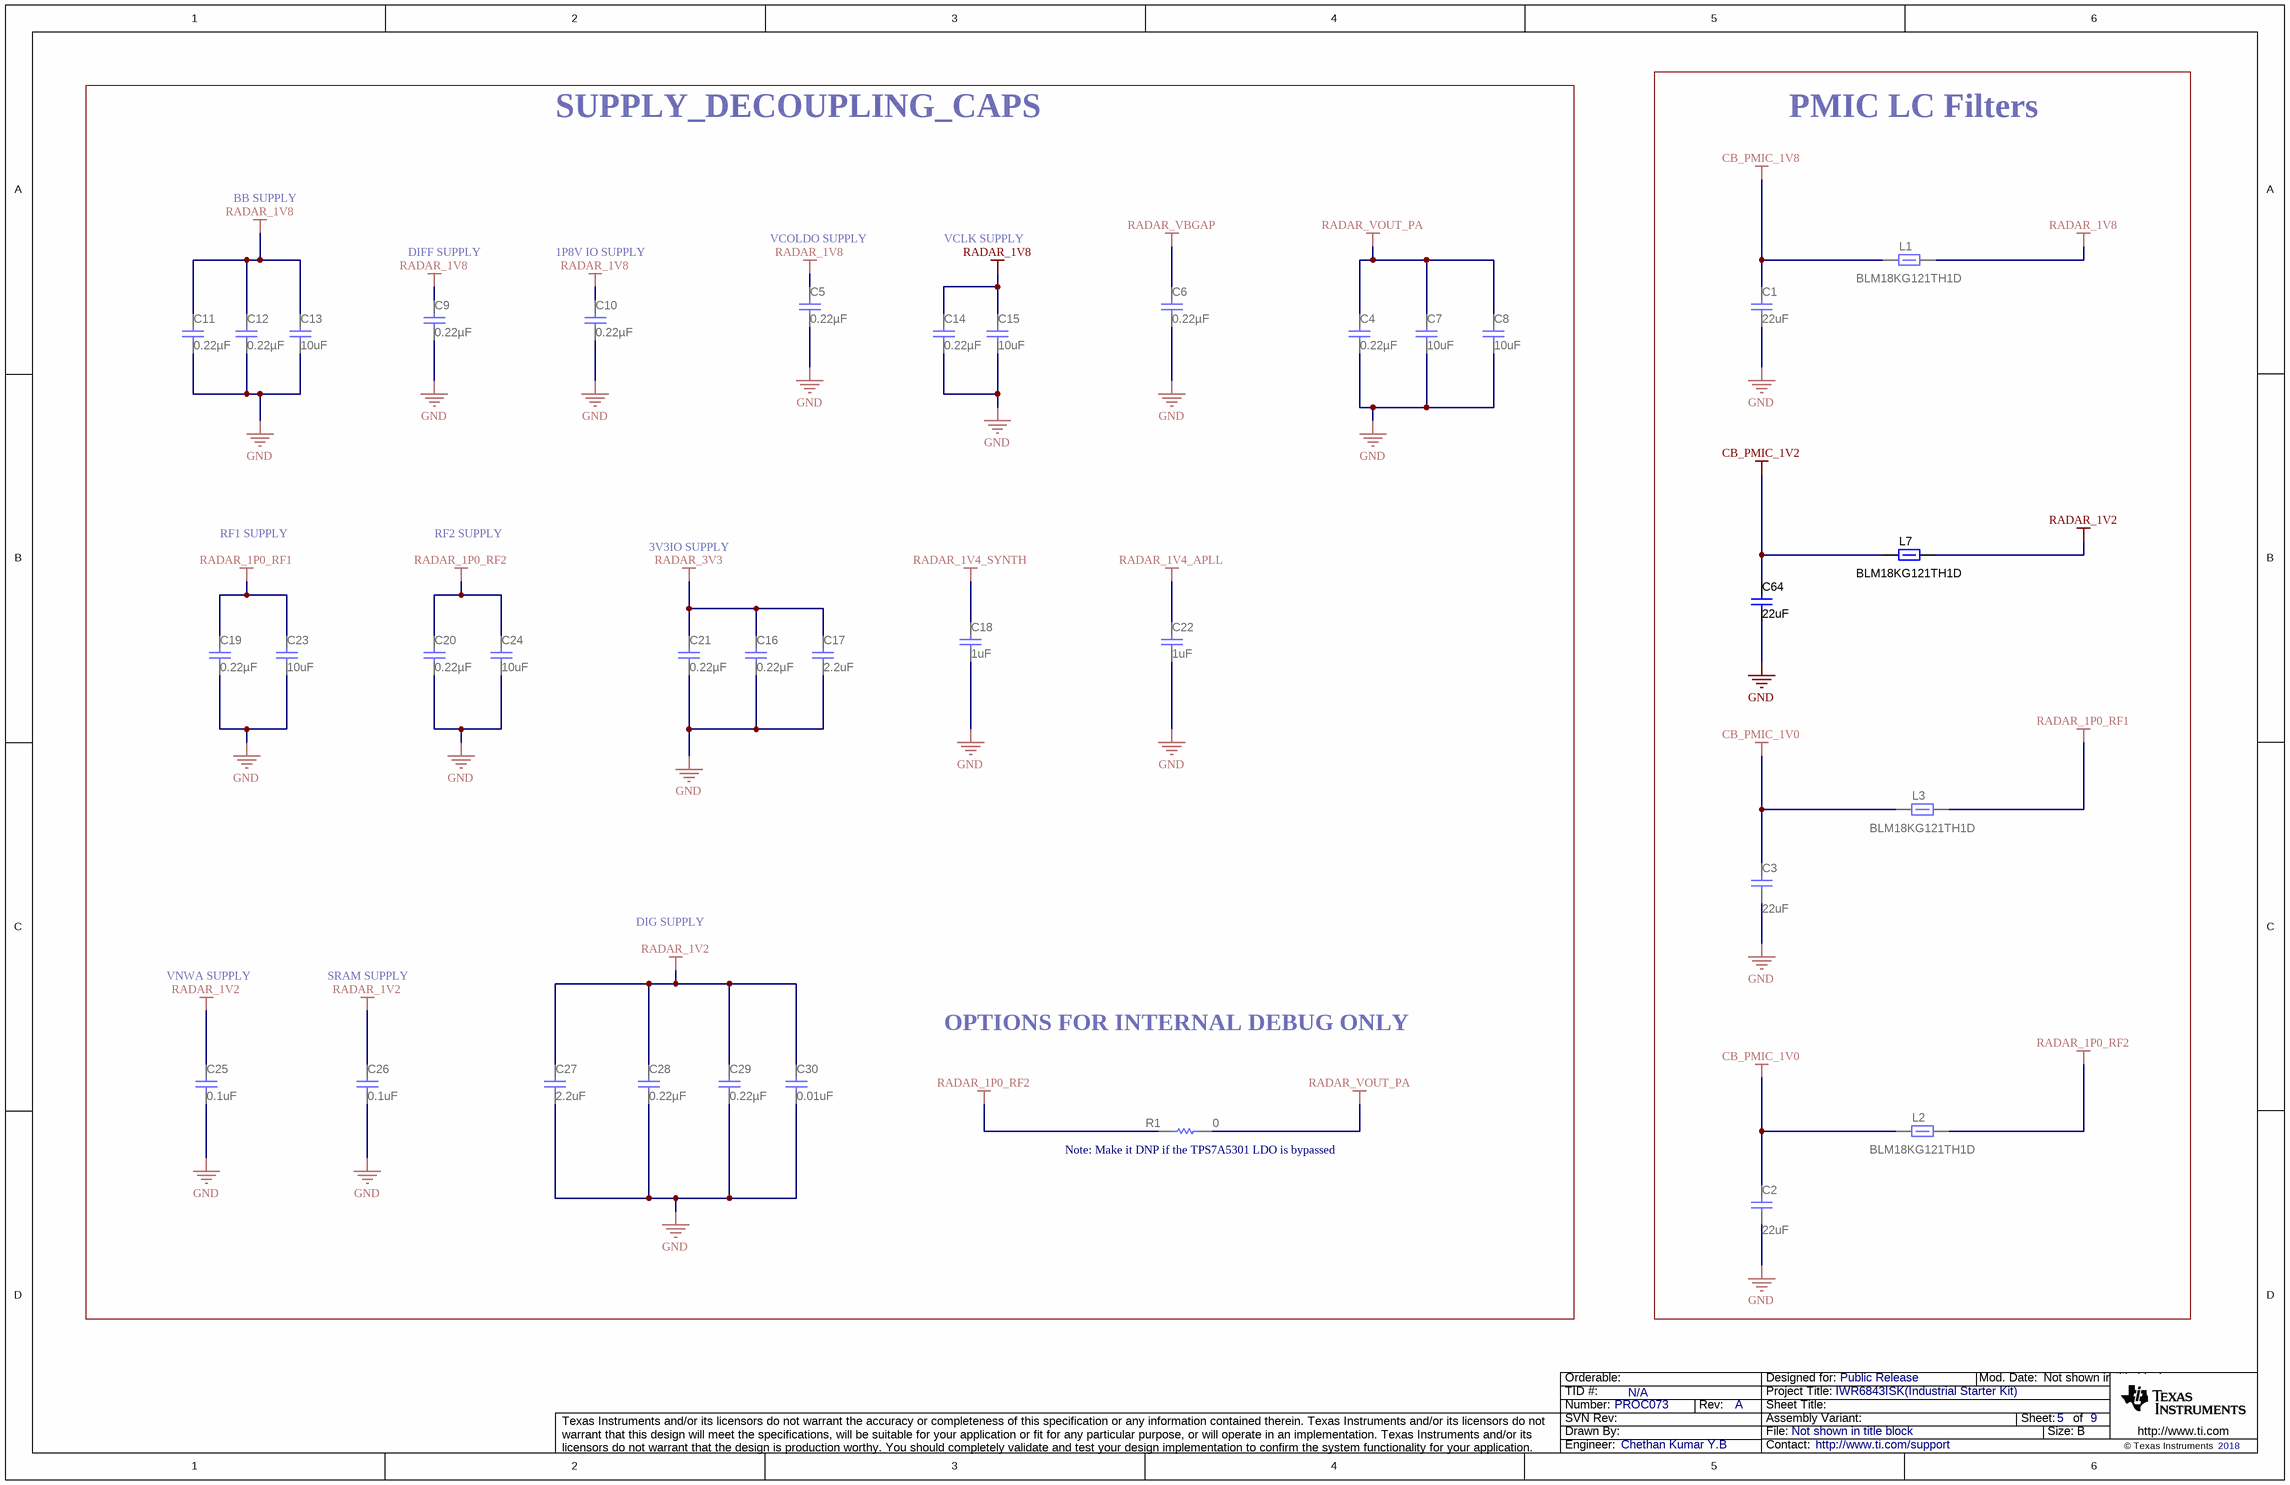
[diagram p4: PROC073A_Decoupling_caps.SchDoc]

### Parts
C1  ValueDisplayed: 22uF  [1206_180]  (hidden comment: CGA5L1X7R0J226M160AC)
C2  ValueDisplayed: 22uF  [1206_180]  (hidden comment: CGA5L1X7R0J226M160AC)
C3  ValueDisplayed: 22uF  [1206_180]  (hidden comment: CGA5L1X7R0J226M160AC)
C4  ValueDisplayed: 0.22µF  [0402L]  (hidden comment: GCM155R71C224KE02D)
C5  ValueDisplayed: 0.22µF  [0402L]  (hidden comment: GCM155R71C224KE02D)
C6  ValueDisplayed: 0.22µF  [0402L]  (hidden comment: GCM155R71C224KE02D)
C7  ValueDisplayed: 10uF  [0805_HV]  (hidden comment: GCM21BR71A106KE22L)
C8  ValueDisplayed: 10uF  [0805_HV]  (hidden comment: GCM21BR71A106KE22L)
C9  ValueDisplayed: 0.22µF  [0402L]  (hidden comment: GCM155R71C224KE02D)
C10  ValueDisplayed: 0.22µF  [0402L]  (hidden comment: GCM155R71C224KE02D)
C11  ValueDisplayed: 0.22µF  [0402L]  (hidden comment: GCM155R71C224KE02D)
C12  ValueDisplayed: 0.22µF  [0402L]  (hidden comment: GCM155R71C224KE02D)
C13  ValueDisplayed: 10uF  [0805_HV]  (hidden comment: GCM21BR71A106KE22L)
C14  ValueDisplayed: 0.22µF  [0402L]  (hidden comment: GCM155R71C224KE02D)
C15  ValueDisplayed: 10uF  [0805_HV]  (hidden comment: GCM21BR71A106KE22L)
C16  ValueDisplayed: 0.22µF  [0402L]  (hidden comment: GCM155R71C224KE02D)
C17  ValueDisplayed: 2.2uF  [0603]  (hidden comment: GCM188R70J225KE22D)
C18  ValueDisplayed: 1uF  [0603]  (hidden comment: GCM188R71C105KA64D)
C19  ValueDisplayed: 0.22µF  [0402L]  (hidden comment: GCM155R71C224KE02D)
C20  ValueDisplayed: 0.22µF  [0402L]  (hidden comment: GCM155R71C224KE02D)
C21  ValueDisplayed: 0.22µF  [0402L]  (hidden comment: GCM155R71C224KE02D)
C22  ValueDisplayed: 1uF  [0603]  (hidden comment: GCM188R71C105KA64D)
C23  ValueDisplayed: 10uF  [0805_HV]  (hidden comment: GCM21BR71A106KE22L)
C24  ValueDisplayed: 10uF  [0805_HV]  (hidden comment: GCM21BR71A106KE22L)
C25  ValueDisplayed: 0.1uF  [0402L]  (hidden comment: GCM155R71C104KA55D)
C26  ValueDisplayed: 0.1uF  [0402L]  (hidden comment: GCM155R71C104KA55D)
C27  ValueDisplayed: 2.2uF  [0603]  (hidden comment: GCM188R70J225KE22D)
C28  ValueDisplayed: 0.22µF  [0402L]  (hidden comment: GCM155R71C224KE02D)
C29  ValueDisplayed: 0.22µF  [0402L]  (hidden comment: GCM155R71C224KE02D)
C30  ValueDisplayed: 0.01uF  [0402L]  (hidden comment: GCM155R71E103KA37D)
C64  ValueDisplayed: 22uF  [1206_180]  (hidden comment: CGA5L1X7R0J226M160AC)
L1  BLM18KG121TH1D  [0603]
L2  BLM18KG121TH1D  [0603]
L3  BLM18KG121TH1D  [0603]
L7  BLM18KG121TH1D  [0603]
R1  ValueDisplayed: 0  [0603]  (hidden comment: MCT06030Z0000ZP500)

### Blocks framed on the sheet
SUPPLY_DECOUPLING_CAPS: C4-C30 R1
PMIC LC Filters: C1-C3 C64 L1-L3 L7

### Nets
CB_PMIC_1V0: C2.2 C3.2 L2.1 L3.1
CB_PMIC_1V2: C64.2 L7.1
CB_PMIC_1V8: C1.2 L1.1
GND: C1.1 C2.1 C3.1 C4.1 C5.1 C6.1 C7.1 C8.1 C9.1 C10.1 C11.1 C12.1 C13.1 C14.1 C15.1 C16.1 C17.1 C18.1 C19.1 C20.1 C21.1 C22.1 C23.1 C24.1 C25.1 C26.1 C27.1 C28.1 C29.1 C30.2 C64.1
RADAR_1P0_RF1: C19.2 C23.2 L3.2
RADAR_1P0_RF2: C20.2 C24.2 L2.2 R1.1
RADAR_1V2: C25.2 C26.2 C27.2 C28.2 C29.2 C30.1 L7.2
RADAR_1V4_APLL: C22.2
RADAR_1V4_SYNTH: C18.2
RADAR_1V8: C5.2 C9.2 C10.2 C11.2 C12.2 C13.2 C14.2 C15.2 L1.2
RADAR_3V3: C16.2 C17.2 C21.2
RADAR_VBGAP: C6.2
RADAR_VOUT_PA: C4.2 C7.2 C8.2 R1.2

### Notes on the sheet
- BB SUPPLY
- DIFF SUPPLY
- 1P8V IO SUPPLY
- VCOLDO SUPPLY
- VCLK SUPPLY
- RF1 SUPPLY
- RF2 SUPPLY
- 3V3IO SUPPLY
- DIG SUPPLY
- VNWA SUPPLY
- SRAM SUPPLY
- OPTIONS FOR INTERNAL DEBUG ONLY
- (near R1) Note: Make it DNP if the TPS7A5301 LDO is bypassed

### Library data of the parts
C1-C3 C64 = CMP-0008770-2: CAP, CERM, 22 uF, 6.3 V, +/- 10%, X7R, AEC-Q200 Grade 1, 1206; Manufacturer: TDK; TaMin_C: -55°C; ESR_ohm: 1.872m; Polarized: N; SizeAreaWB_mm2: 10.92; Value1: 0.001872 ohm; U/M: EA; Value: 22uF; SizeZ_mm: 1.8; SizeX_mm: 3.2; SizeY_mm: 1.6; Value2: 6.3V; SizeArea_mm2: 5.12; CompType: Capacitor; AEC Qualified: Y; Cap_F: 22µF; IRMS_A: 5.30203A; AEC Grade: 1; AEC Category: Q200; TaMax_C: 125°C; INSTALLATION: DNP
C4-C6 C9-C12 C14 C16 C19-C21 C28 C29 = CMP-0078265-1: CAP, CERM, 0.22 µF, 16 V,+/- 10%, X7R, AEC-Q200 Grade 1, 0402; Manufacturer: MuRata; TaMin_C: -55°C; Polarized: N; SizeAreaWB_mm2: 3; U/M: EA; Value: 0.22uF; TaMax_C: 125°C; SizeZ_mm: 0.6; SizeX_mm: 1; SizeY_mm: 0.5; Cap_Case: 0402; Value2: 16V; CompType: Capacitor; AEC Qualified: Y; Cap_F: 220nF; AEC Category: Q200
C7 C13 C15 C23 C24 = CMP-0008017-2: as C45 on sheet PROC073A_PMIC
C8 = CMP-0008017-2: CAP, CERM, 10 uF, 10 V, +/- 10%, X7R, 0805; Manufacturer: MuRata; TaMin_C: -55°C; Polarized: N; SizeAreaWB_mm2: 6.75; Value1: Unknown; U/M: EA; Value: 10uF; TaMax_C: 125°C; SizeZ_mm: 1.45; SizeX_mm: 2; SizeY_mm: 1.25; Cap_Case: 0805; Value2: 10V; SizeArea_mm2: 2.5; CompType: Capacitor; Cap_F: 10µF; AEC Category: Q200; INSTALLATION: DNP
C17 C27 = CMP-0007134-5: CAP, CERM, 2.2 uF, 6.3 V, +/- 10%, X7R, AEC-Q200 Grade 1, 0603; Manufacturer: MuRata; TaMin_C: -55°C; Polarized: N; SizeAreaWB_mm2: 4.68; Value1: Unknown; U/M: EA; Value: 2.2uF; TaMax_C: 125°C; SizeZ_mm: 1; SizeX_mm: 1.6; SizeY_mm: 0.8; Value2: 6.3V; SizeArea_mm2: 1.28; CompType: Capacitor; AEC Qualified: Y; Cap_F: 2.2µF; AEC Category: Q200
C18 C22 = CMP-0007136-5: CAP, CERM, 1 uF, 16 V, +/- 10%, X7R, AEC-Q200 Grade 1, 0603; Manufacturer: MuRata; TaMin_C: -55°C; Polarized: N; SizeAreaWB_mm2: 4.68; Value1: Unknown; U/M: EA; Value: 1uF; TaMax_C: 125°C; SizeZ_mm: 1; SizeX_mm: 1.6; SizeY_mm: 0.8; Value2: 16V; SizeArea_mm2: 1.28; CompType: Capacitor; AEC Qualified: Y; Cap_F: 1µF; AEC Category: Q200
C25 C26 = CMP-0006351-2: CAP, CERM, 0.1 uF, 16 V, +/- 10%, X7R, 0402; Manufacturer: MuRata; TaMin_C: -55°C; Polarized: N; SizeAreaWB_mm2: 3; Value1: Unknown; U/M: EA; Value: 0.1uF; TaMax_C: 125°C; SizeZ_mm: 0.6; SizeX_mm: 1; SizeY_mm: 0.5; Cap_Case: 0402; Value2: 16V; CompType: Capacitor; Cap_F: 100nF; AEC Category: Q200
C30 = CMP-0006352-2: CAP, CERM, 0.01 uF, 25 V, +/- 10%, X7R, 0402; Manufacturer: MuRata; TaMin_C: -55°C; Polarized: N; SizeAreaWB_mm2: 3; Value1: Unknown; U/M: EA; Value: 0.01uF; TaMax_C: 125°C; SizeZ_mm: 0.6; SizeX_mm: 1; SizeY_mm: 0.5; Cap_Case: 0402; Value2: 25V; CompType: Capacitor; Cap_F: 10nF; AEC Category: Q200
L1-L3 L7 = CMP-0077879-2: Ferrite Bead, 120 ohm @ 100 MHz, 1.9 A, 0603; Manufacturer: MuRata; ZTyp@100MHz_Ohm: 120; SizeAreaWB_mm2: 4.68; DCR_ohm: 0.04; Value1: 0.04 ohm; Value: 120 ohm; Imax_A: 1.9A; SizeZ_mm: 1.0; SizeX_mm: 1.6; SizeY_mm: 0.8; SizeArea_mm2: 1.28
R1 = CMP-0025884-3: as R99 on sheet PROC073A_PMIC

## Sheet PROC073A_QSPI_Flash_section.SchDoc
size 431 x 279 mm; Date: Not shown in title block; ApprovedBy: Not shown in title block; CheckedBy: Not shown in title block; Author: Not shown in title block; CompanyName: Not shown in title block; Engineer: Not shown in title block; Organization: Not shown in title block; Address1: Not shown in title block; Address2: Not shown in title block; Address3: Not shown in title block; Address4: Not shown in title block; DocumentNumber: 1; Revision: Use project parameter SCH_Rev; SheetNumber: 6; SheetTotal: 9; PageSetup: Record=PageOptions¦CenterHorizontal=True¦CenterVertical=True¦PrintScale=1.00¦XCorrection=1.00¦YCorrection=1.00¦PrintKind=0¦BorderSize=5000000¦LeftOffset=0¦BottomOffset=0¦Orientation=2¦PaperLength=1000¦PaperWidth=1000¦Scale=100¦PaperSource=15¦PrintQuality=600¦MediaType=1¦DitherType=10¦PaperKind=Letter¦PrintScaleMode=1
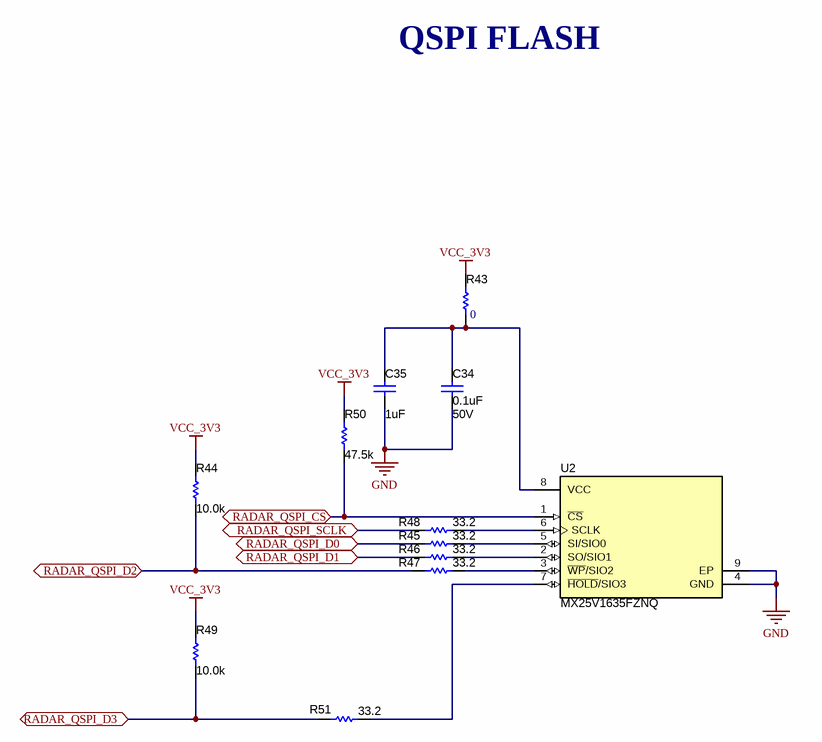
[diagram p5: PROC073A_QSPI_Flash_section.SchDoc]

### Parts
C34  VDC_V: 50V  ValueDisplayed: 0.1uF  [0402L]  (hidden comment: CGA2B3X7R1H104K050BB)
C35  ValueDisplayed: 1uF  [0603]  (hidden comment: GCM188R71C105KA64D)
R43  ValueDisplayed: 0  [0402]  (hidden comment: ERJ-2GE0R00X)
R44  ValueDisplayed: 10.0k  [0402L]  (hidden comment: CRCW040210K0FKED)
R45  ValueDisplayed: 33.2  [0201_Silk]  (hidden comment: CRCW020133R2FNED)
R46  ValueDisplayed: 33.2  [0201_Silk]  (hidden comment: CRCW020133R2FNED)
R47  ValueDisplayed: 33.2  [0201_Silk]  (hidden comment: CRCW020133R2FNED)
R48  ValueDisplayed: 33.2  [0201_Silk]  (hidden comment: CRCW020133R2FNED)
R49  ValueDisplayed: 10.0k  [0402L]  (hidden comment: CRCW040210K0FKED)
R50  ValueDisplayed: 47.5k  [0402L]  (hidden comment: CRCW040247K5FKED)
R51  ValueDisplayed: 33.2  [0201_Silk]  (hidden comment: CRCW020133R2FNED)
U2  MX25V1635FZNQ  [WSON-8L_6x5MM_EP]

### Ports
RADAR_QSPI_CS (bidir), RADAR_QSPI_D0 (bidir), RADAR_QSPI_D1 (bidir), RADAR_QSPI_D2 (bidir), RADAR_QSPI_D3 (bidir), RADAR_QSPI_SCLK (bidir)

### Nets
GND: C34.1 C35.1 U2.4(GND) U2.9(EP)
VCC_3V3: R43.2 R44.2 R49.2 R50.1
RADAR_QSPI_CS: R50.2 U2.1(~{CS}) ; port RADAR_QSPI_CS
RADAR_QSPI_D0: R45.2 ; port RADAR_QSPI_D0
RADAR_QSPI_D1: R46.1 ; port RADAR_QSPI_D1
RADAR_QSPI_D2: R44.1 R47.1 ; port RADAR_QSPI_D2
RADAR_QSPI_D3: R49.1 R51.2 ; port RADAR_QSPI_D3
RADAR_QSPI_SCLK: R48.2 ; port RADAR_QSPI_SCLK
NetC34_2: C34.2 C35.2 R43.1 U2.8(VCC)
NetR45_1: R45.1 U2.5(SI/SIO0)
NetR46_2: R46.2 U2.2(SO/SIO1)
NetR47_2: R47.2 U2.3(~{WP}/SIO2)
NetR48_1: R48.1 U2.6(SCLK)
NetR51_1: R51.1 U2.7(~{HOLD}/SIO3)

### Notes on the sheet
- QSPI FLASH

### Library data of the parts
C34 = CMP-0006325-2: CAP, CERM, 0.1 uF, 50 V, +/- 10%, X7R, AEC-Q200 Grade 1, 0402; Manufacturer: TDK; TaMin_C: -55°C; ESR_ohm: 0.039064; Polarized: N; SizeAreaWB_mm2: 3; Value1: 0.039064 ohm; U/M: EA; Value: 0.1uF; TaMax_C: 125°C; SizeZ_mm: 0.6; SizeX_mm: 1; SizeY_mm: 0.5; Cap_Case: 0402; AEC Qualified: Y; Cap_F: 100nF; IRMS_A: 8.14669dA; AEC Category: Q200
C35 = CMP-0007136-5: as C18 on sheet PROC073A_Decoupling_caps
R43 = CMP-0026992-3: as R72 on sheet PROC073A_IWR6843_Chip
R44 R49 = CMP-0025958-2: as R152 on sheet PROC073A_IWR6843_Chip
R45-R48 R51 = CMP-0027275-2: RES, 33.2, 1%, 0.05 W, 0201; Manufacturer: Vishay-Dale; Power_W: 50mW; TempCo: 200 ppm/C; Value_Code: 33R2; U/M: EA; Value: 33.2; EIA_Code: E96; SizeX_mm: 0.6; SizeY_mm: 0.3; SizeZ_mm: 0.26; Value2: 0.05W; SizeArea_mm2: 0.18; AEC Qualified: N; AEC Category: Q200
R50 = CMP-0026395-1: RES, 47.5 k, 1%, 0.063 W, 0402; Manufacturer: Vishay-Dale; Power_W: 63mW; TempCo: 100 ppm/C; Value_Code: 47k5; U/M: EA; Value: 47.5k; EIA_Code: E96; SizeX_mm: 1; SizeY_mm: 0.5; SizeZ_mm: 0.6; Value2: 0.063W; VDC_V: 50V; AEC Category: Q200
U2 = CMP-0079267-1: 2.3V-3.6V, 16M-BIT [x 1/x 2/x 4] CMOS FLASH Memory, WSON-8; Manufacturer: Macronix International Co., LTD; SizeArea_mm2: 30; SizeAreaWB_mm2: 56; SizeY_mm: 5; SizeZ_mm: 0.8; SizeX_mm: 6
